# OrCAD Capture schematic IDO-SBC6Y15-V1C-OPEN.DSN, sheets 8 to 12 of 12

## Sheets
8 P12 EXPAND: size A2; note: EXPAND
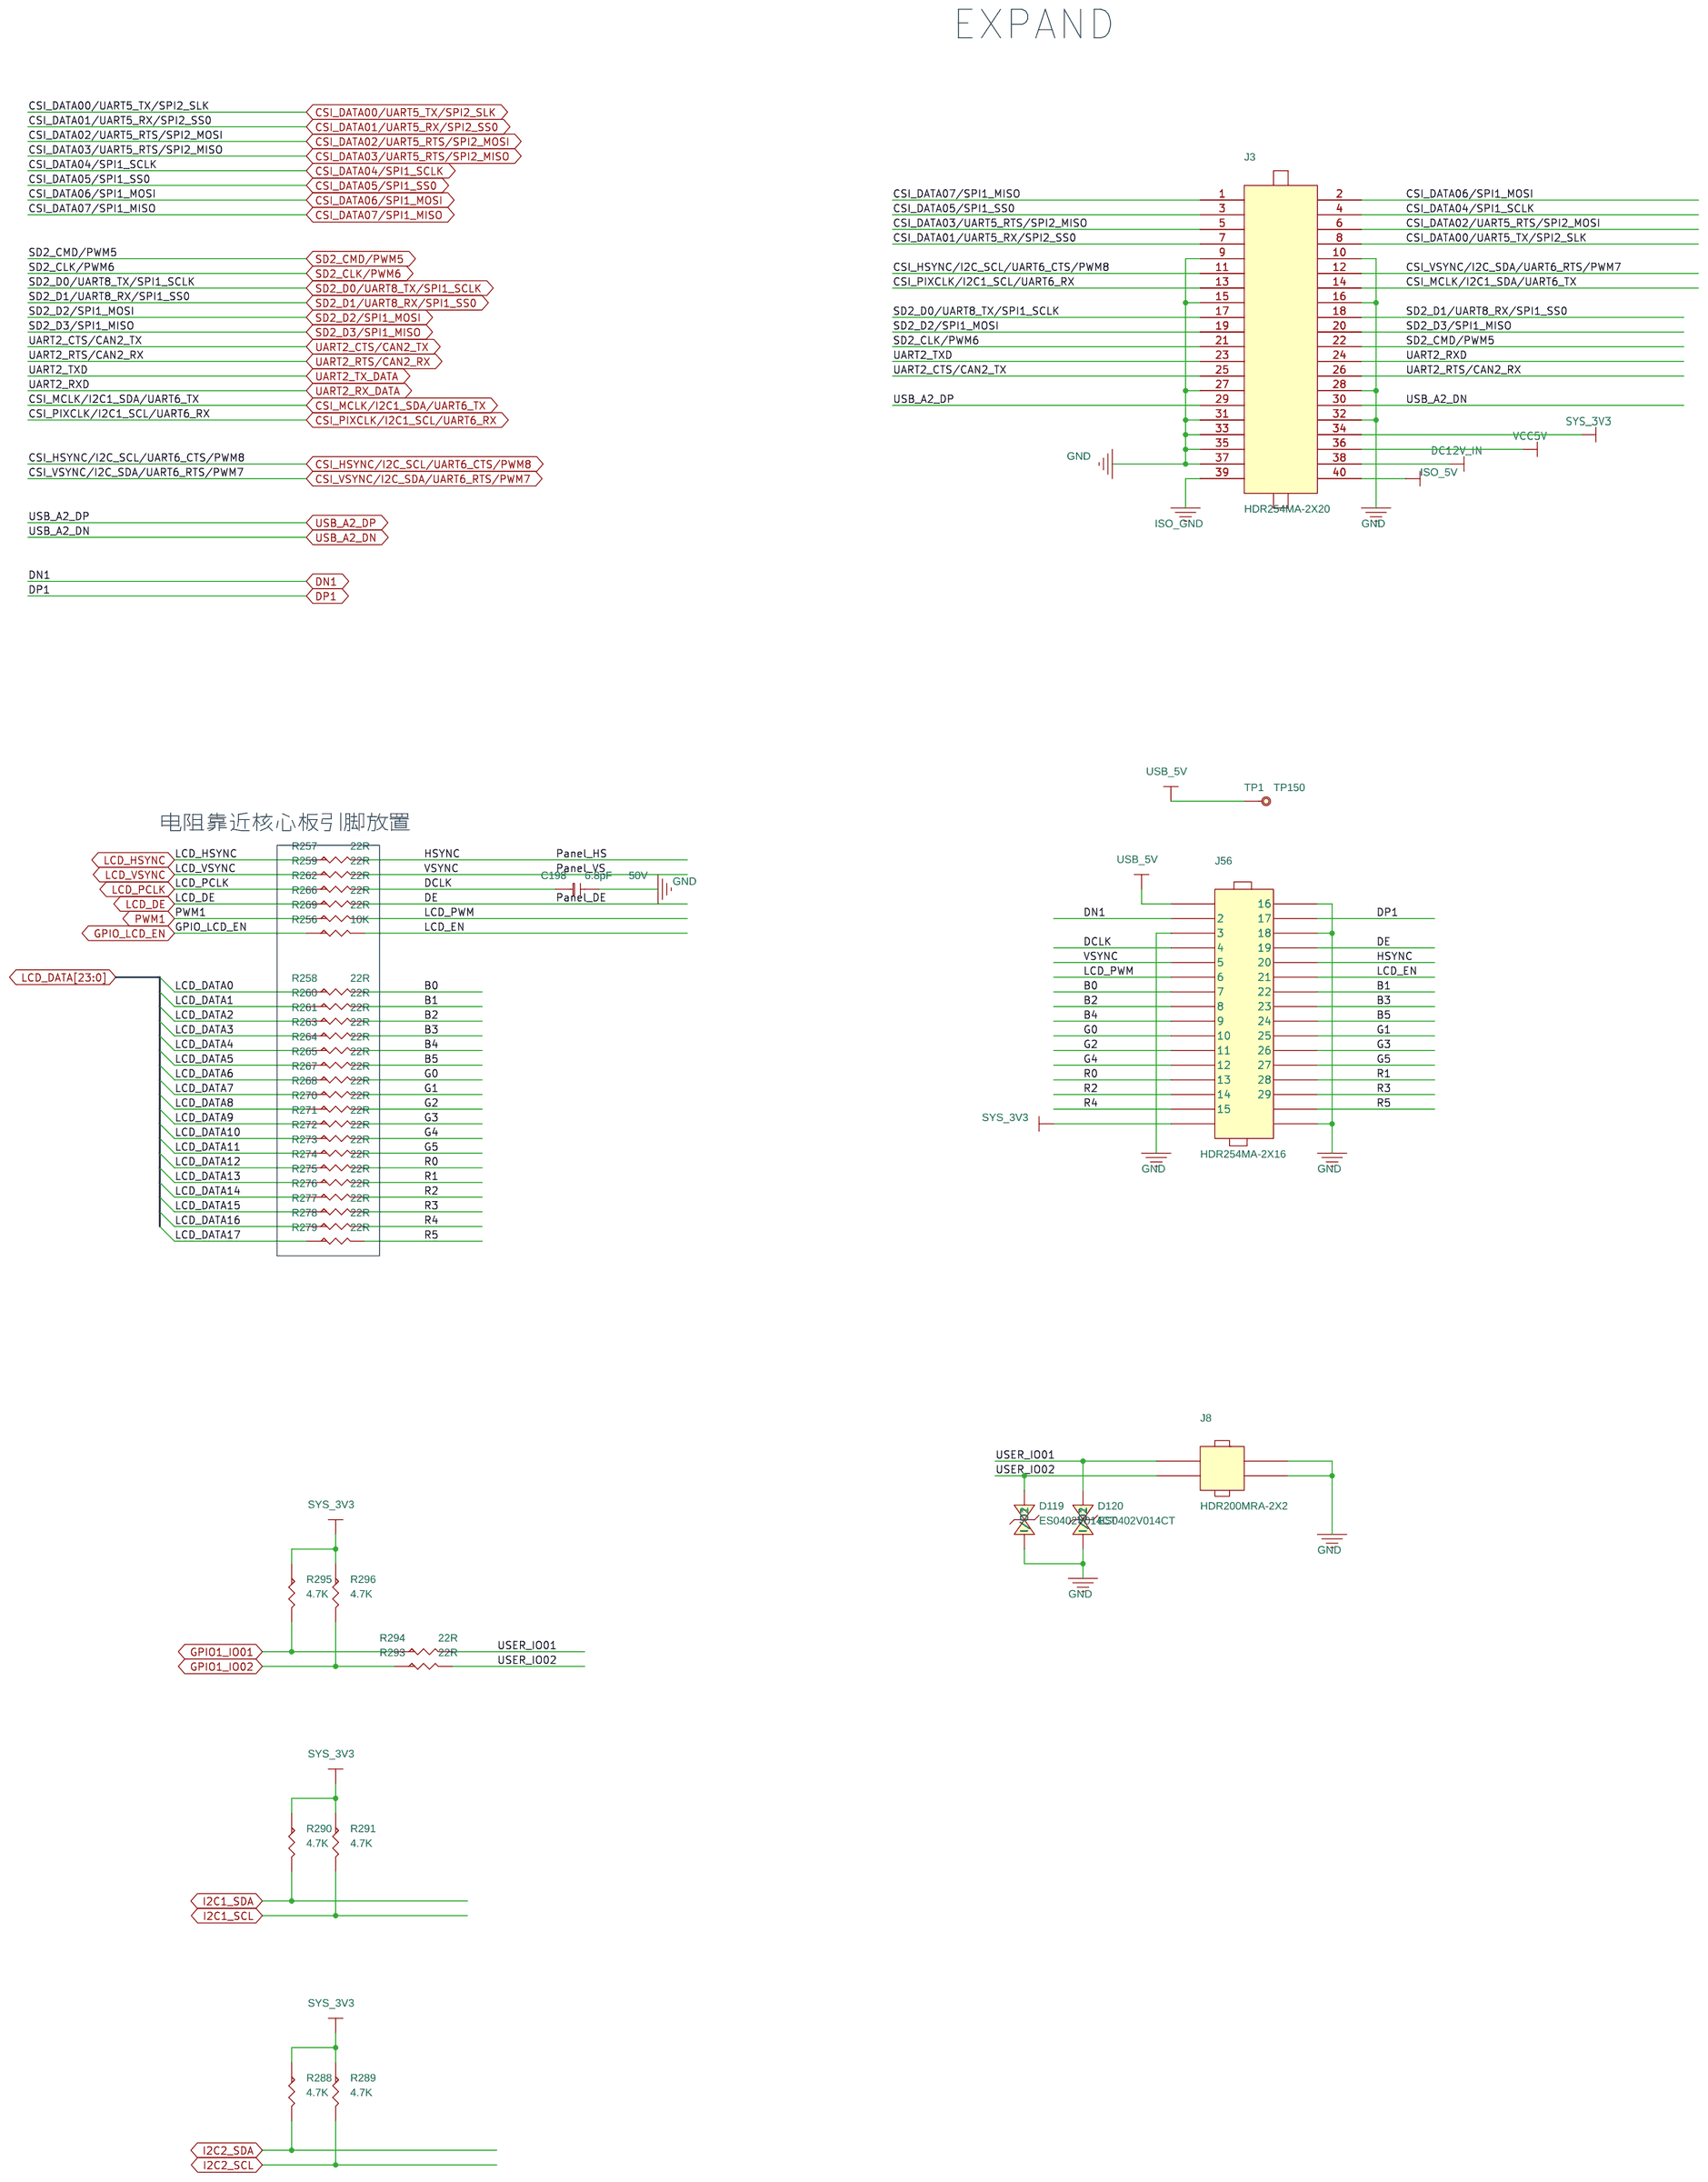
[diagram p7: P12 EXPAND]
9 P11 4G/WIFI: size A2; note: 4G/WIFI
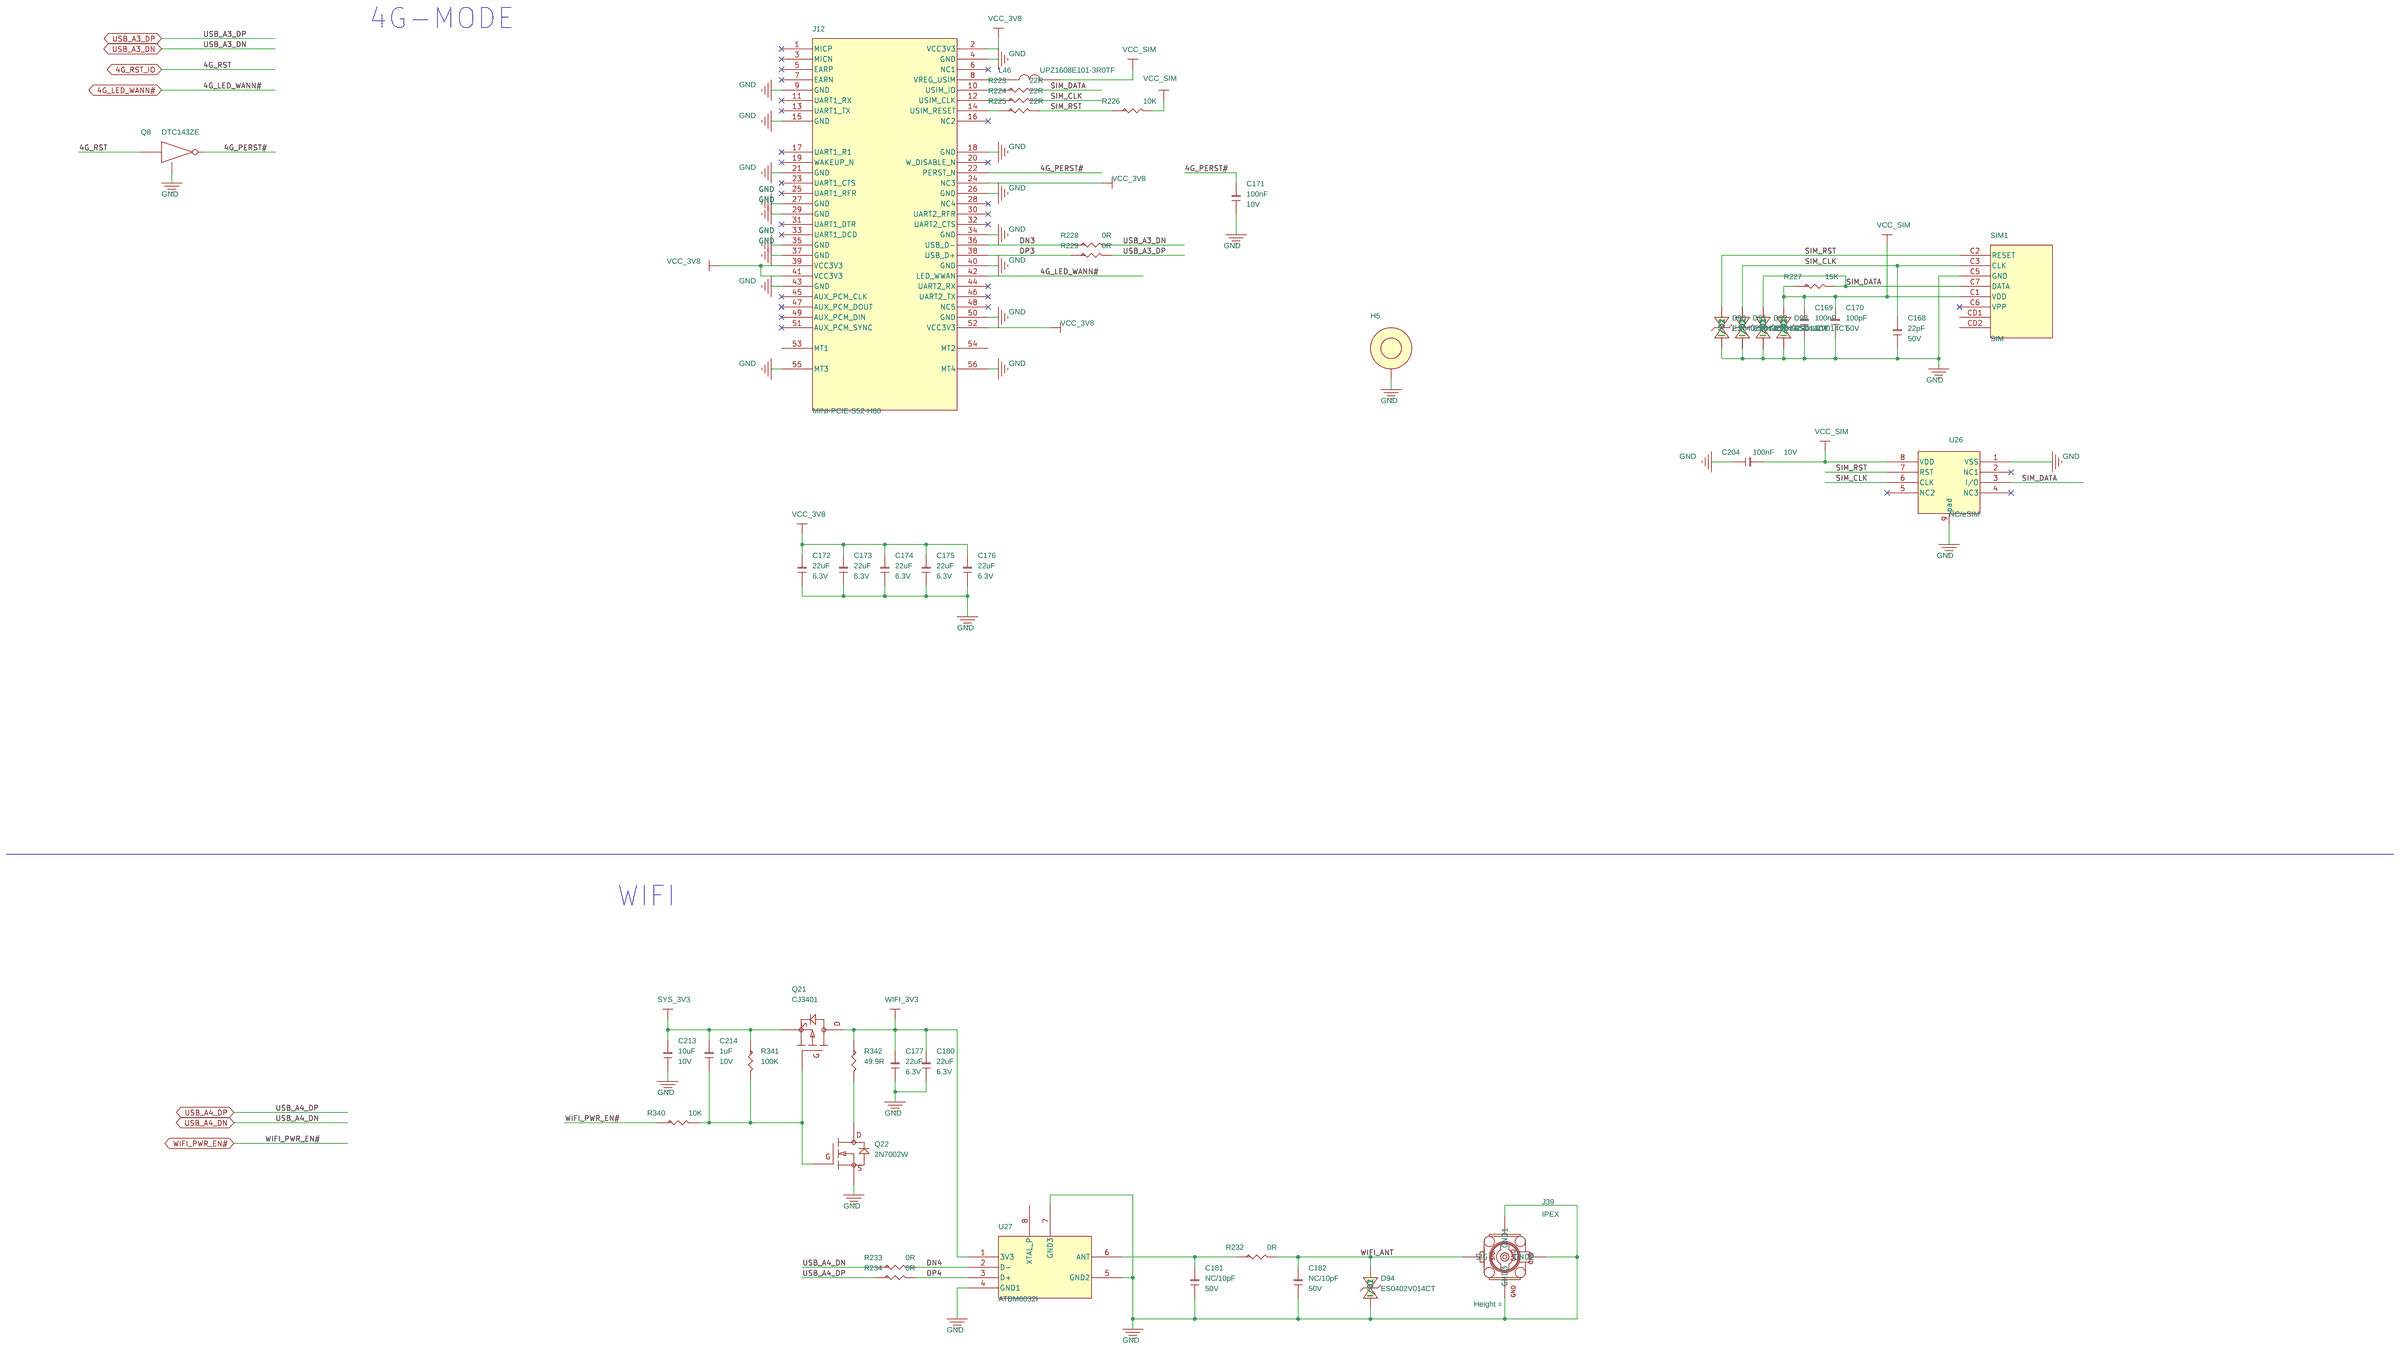
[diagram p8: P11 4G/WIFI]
10 P07 SD/RTC: size A2; note: SD/RTC
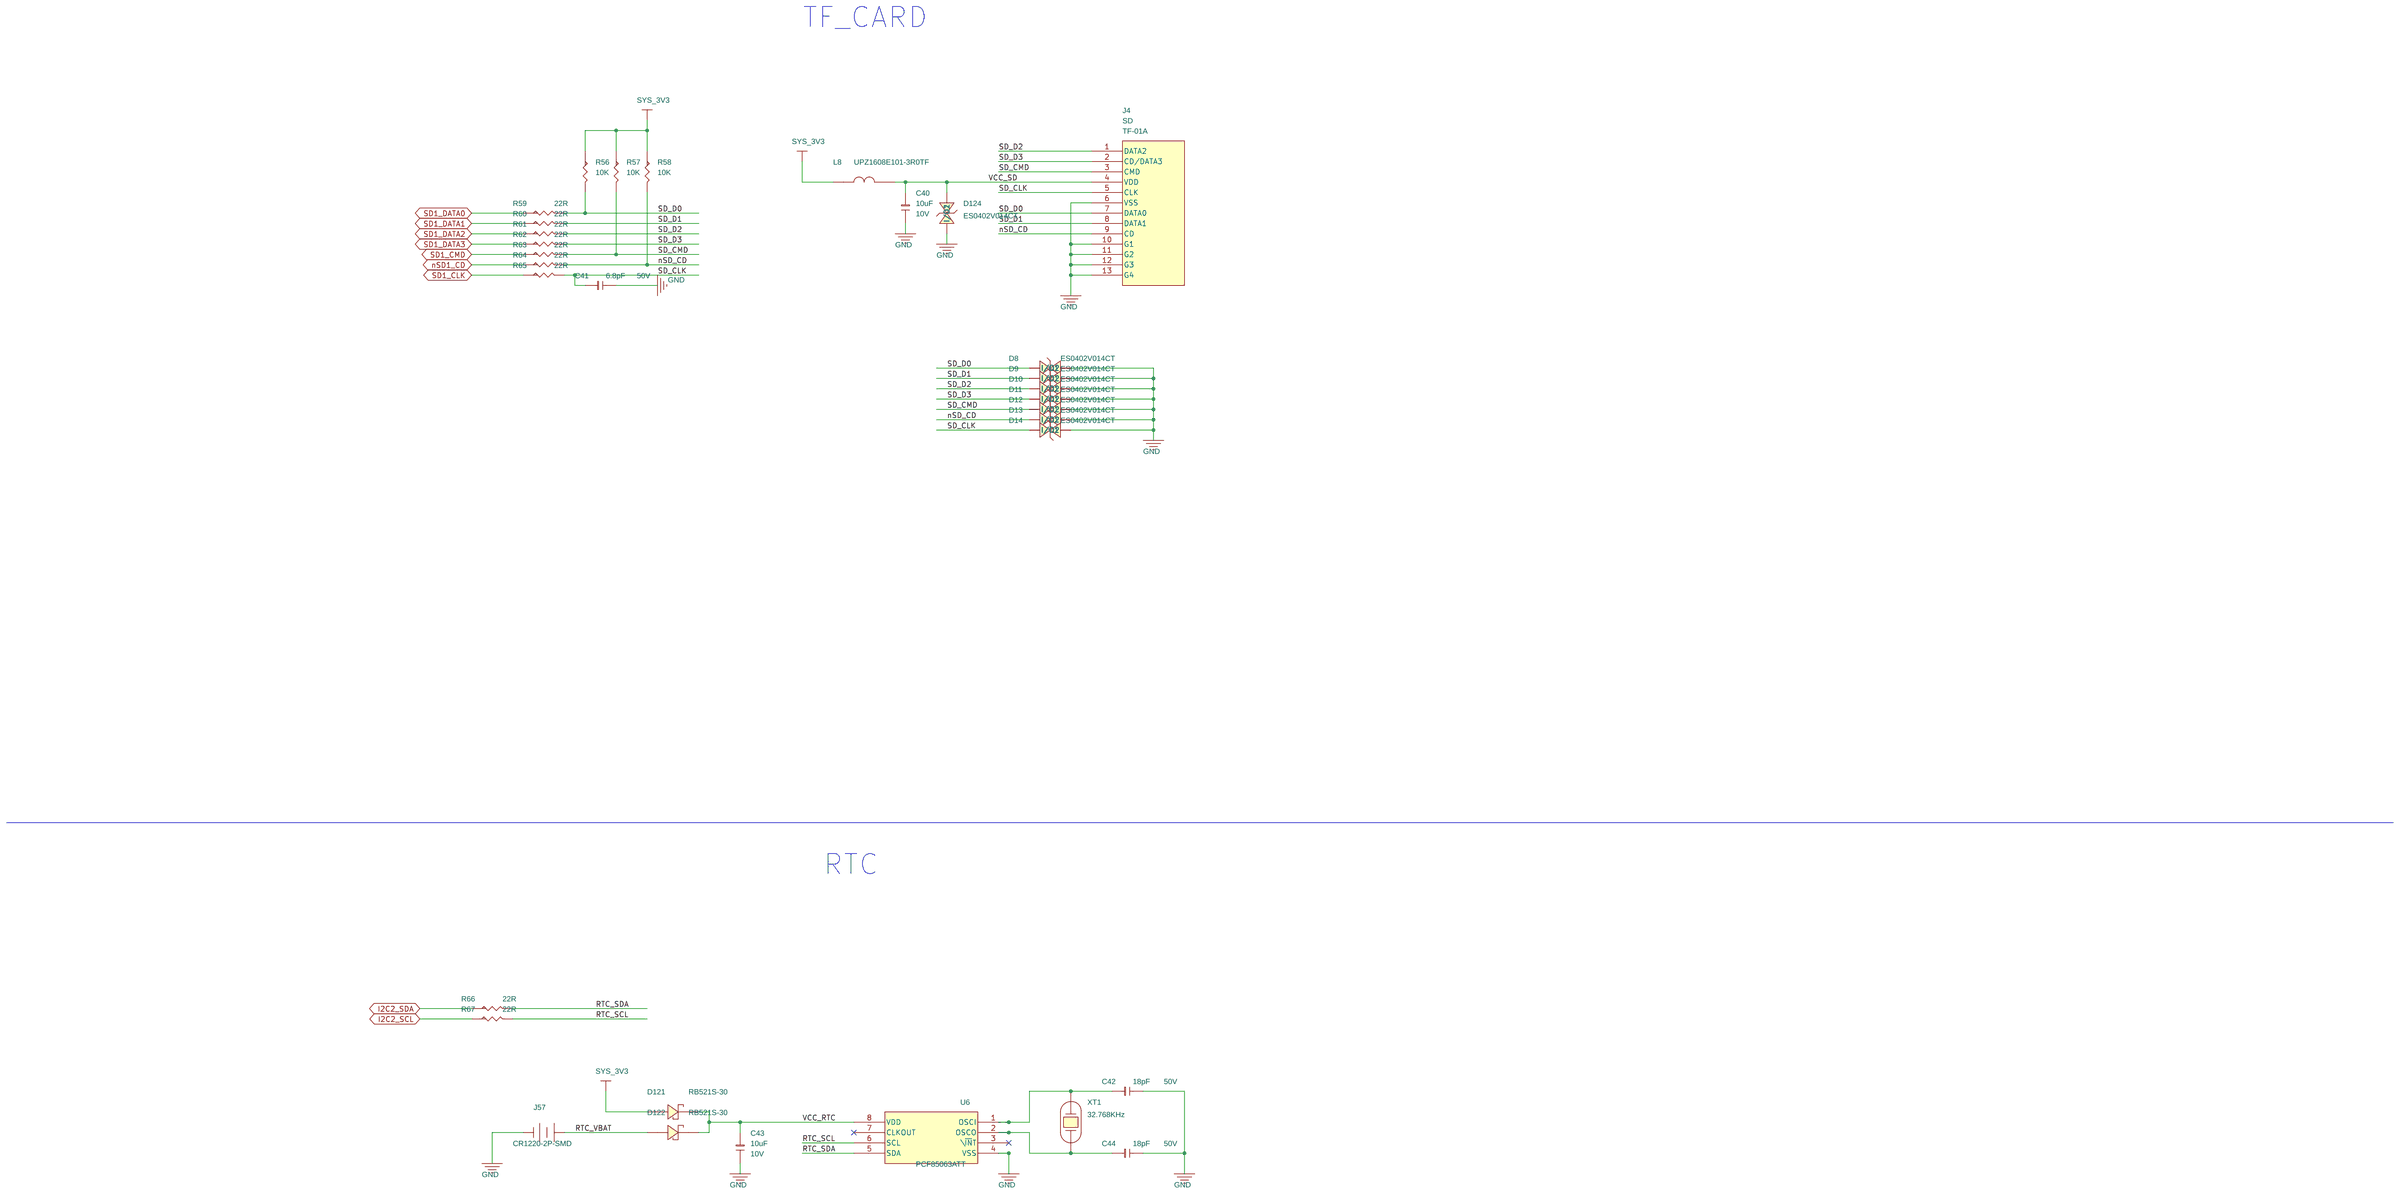
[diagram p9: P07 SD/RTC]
11 P10 UART/Debug: size A2; note: UART/Debug
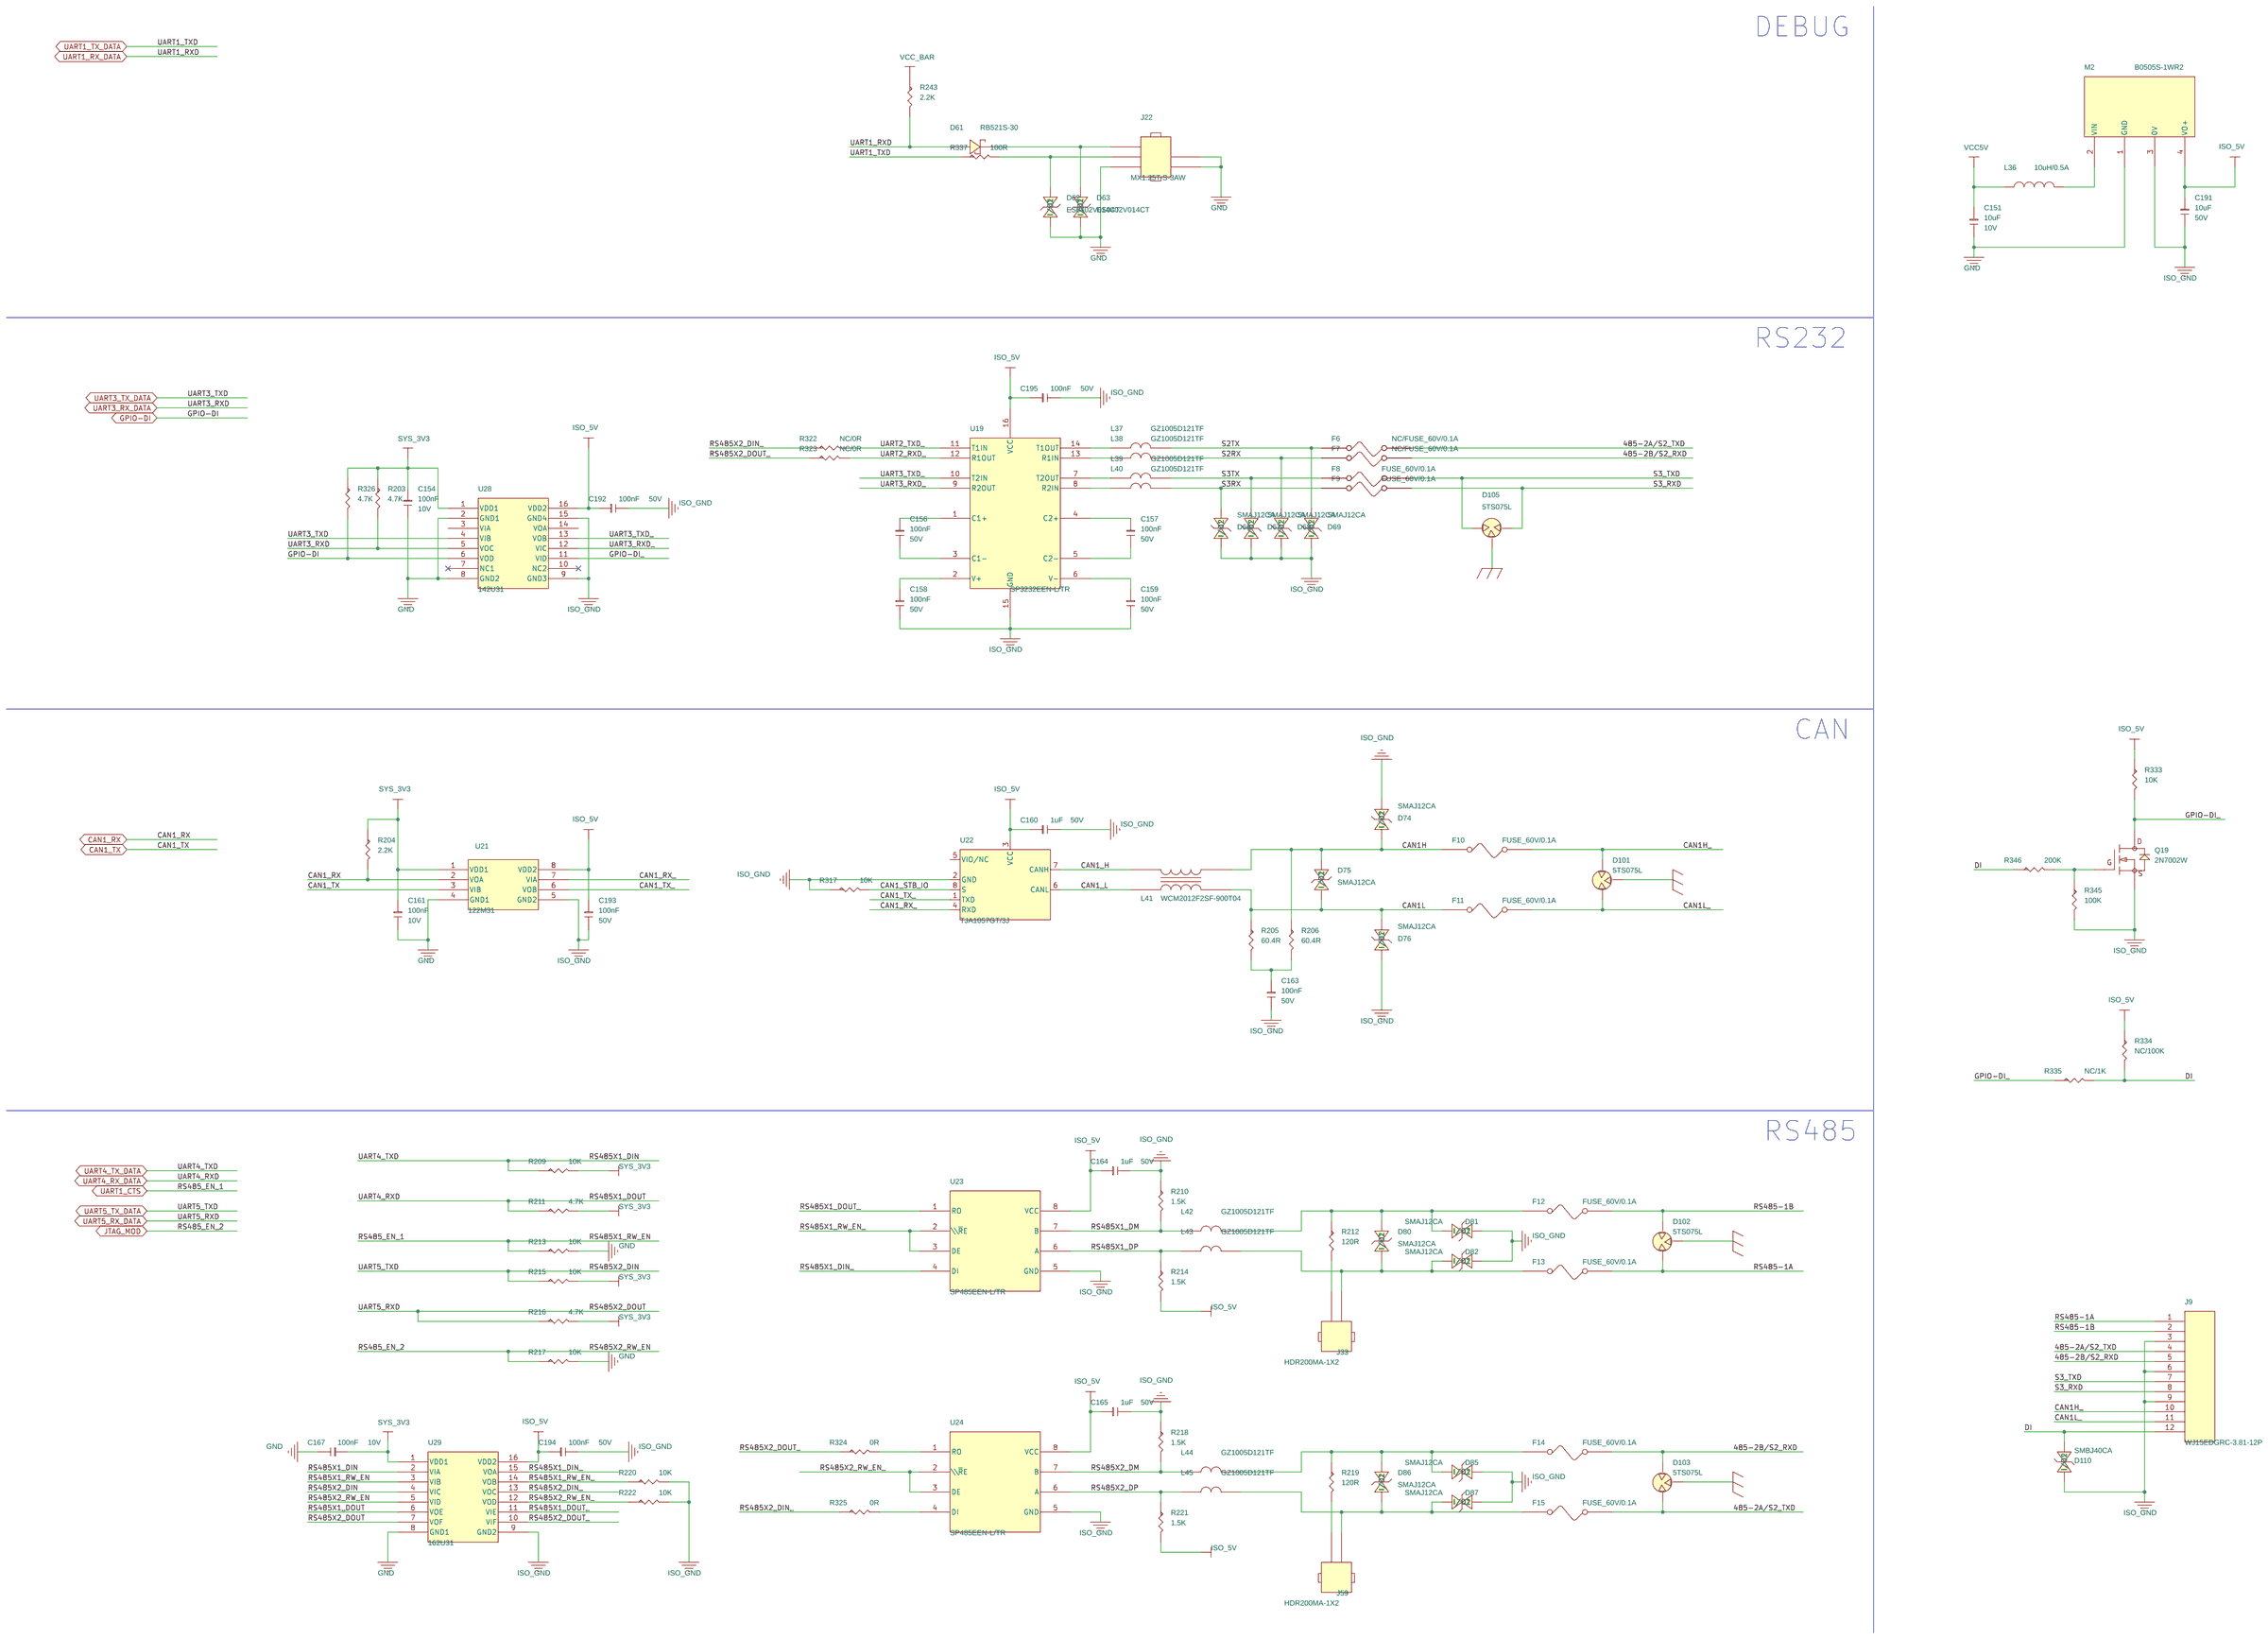
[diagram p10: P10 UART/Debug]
12 P05 POWER_SUPPLY/LED: size A2; note: POWER_SUPPY
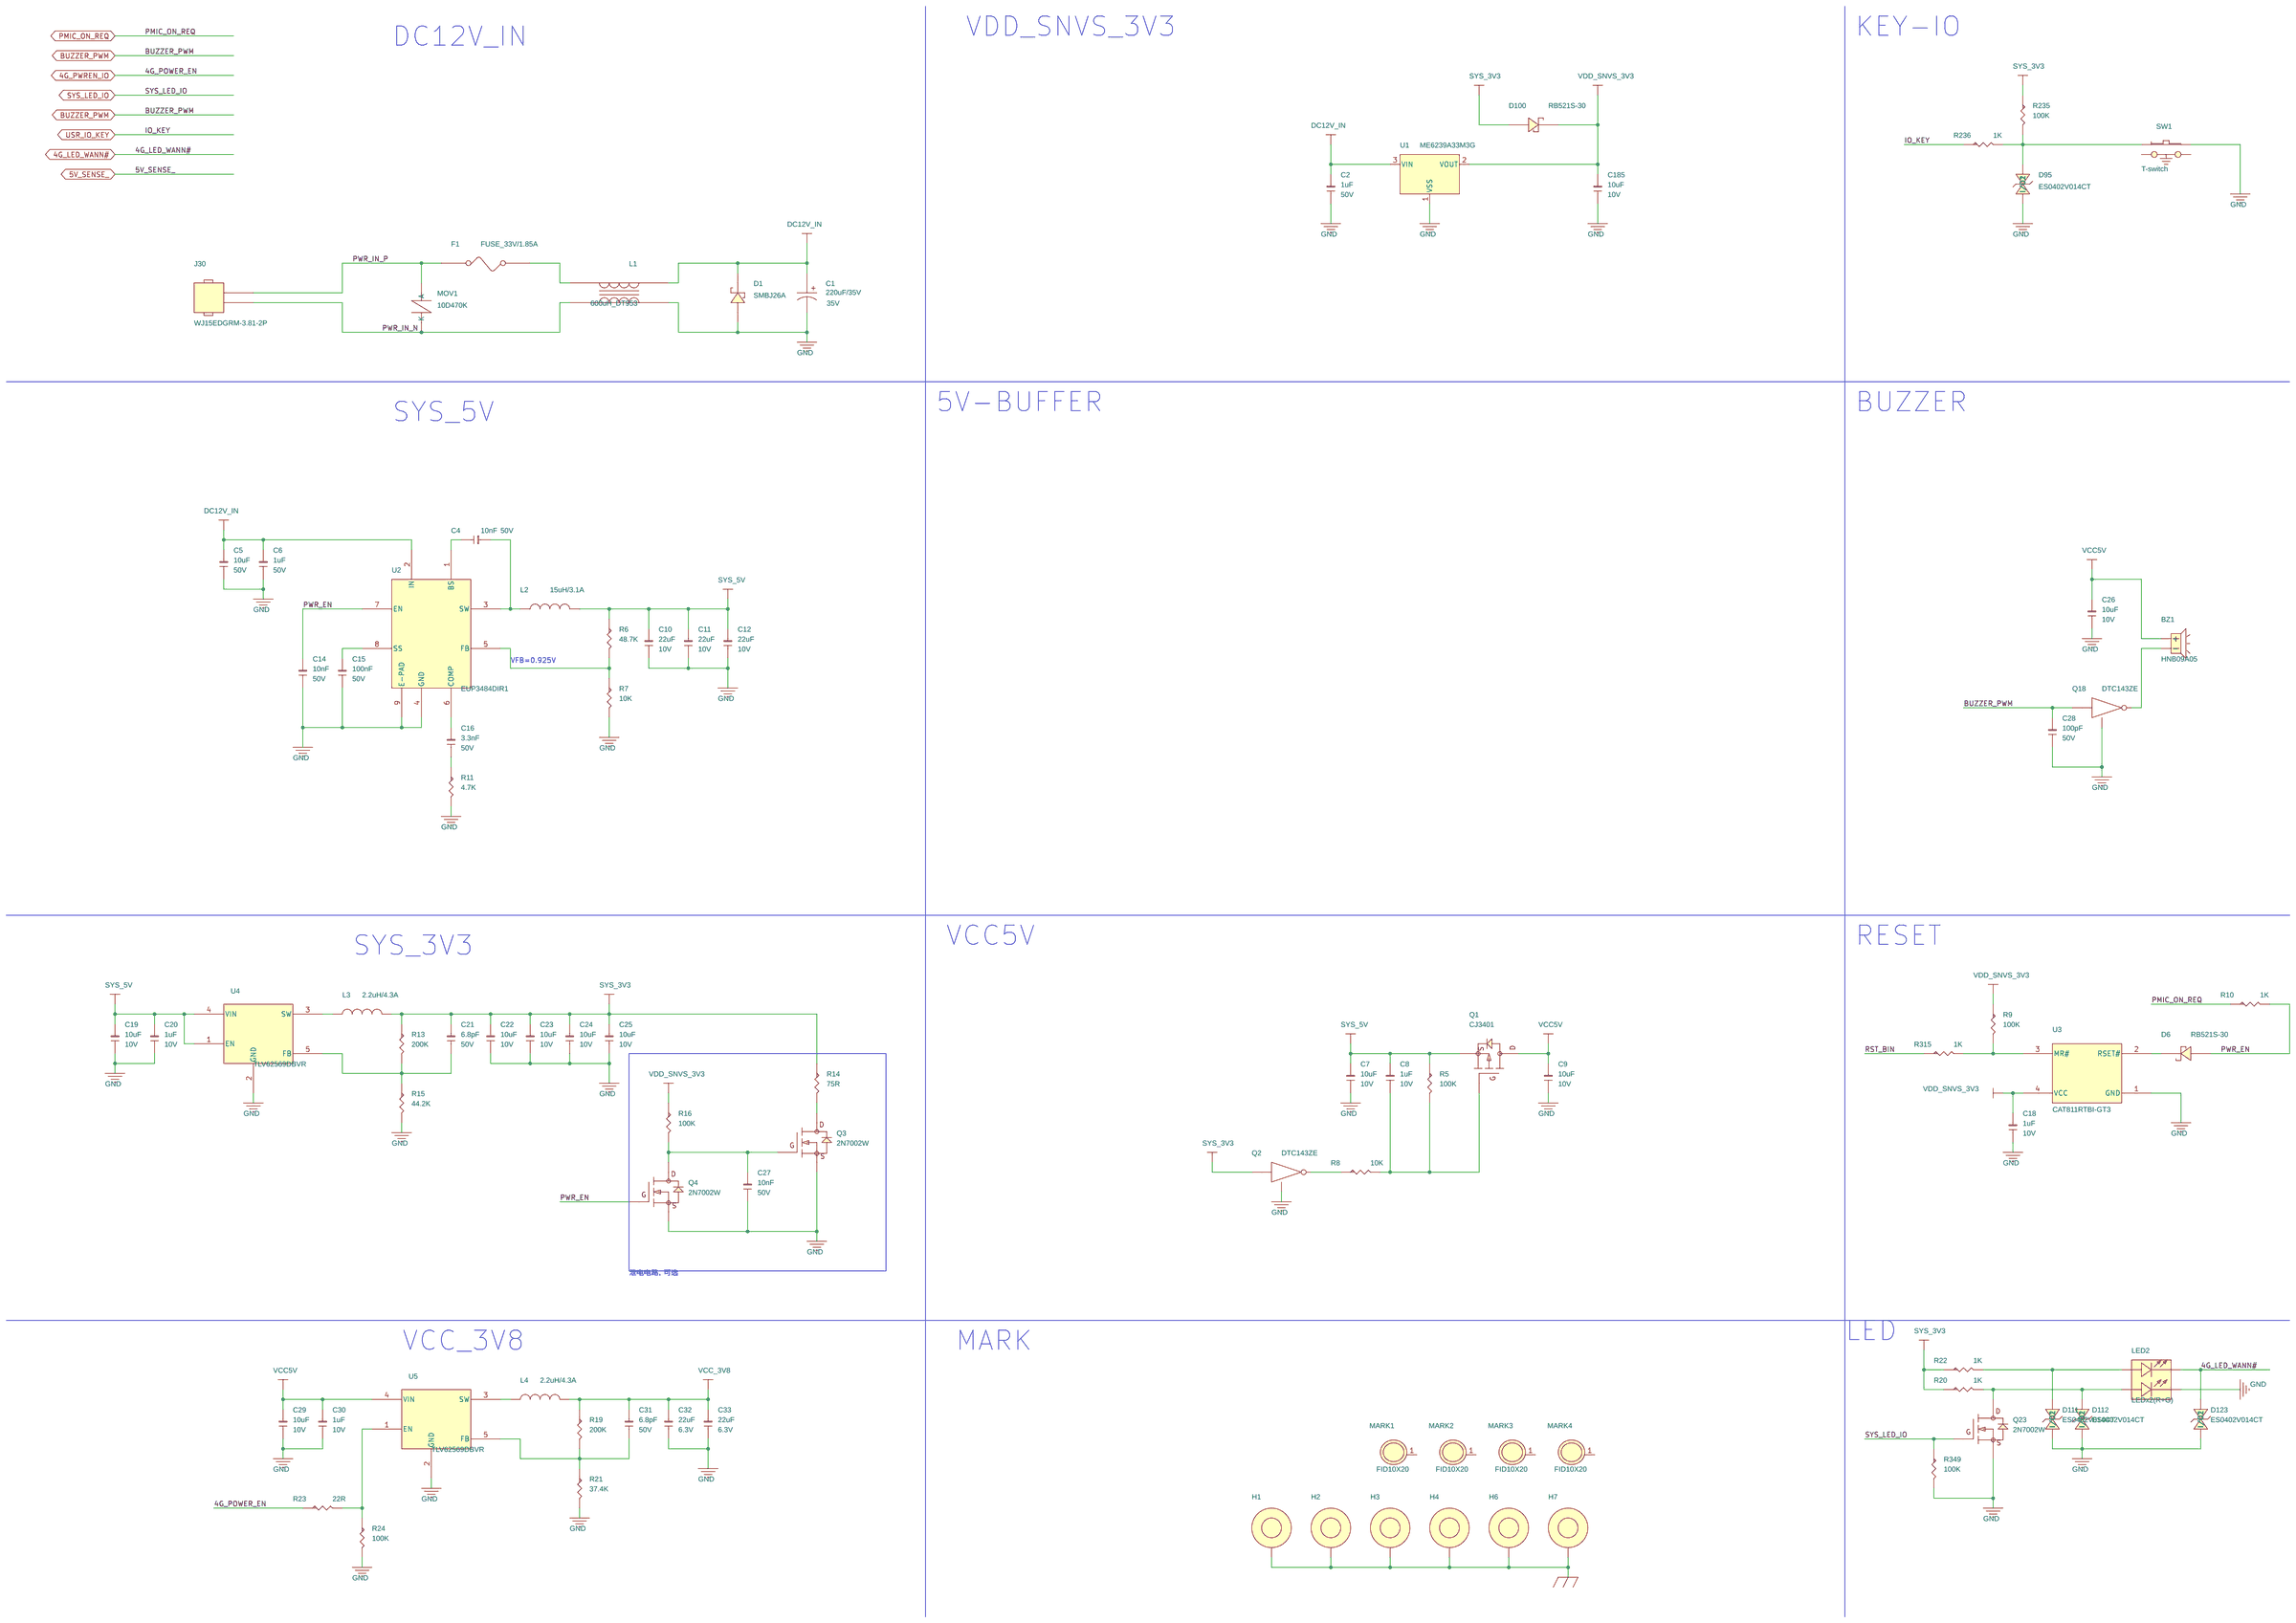
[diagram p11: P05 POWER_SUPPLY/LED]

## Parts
sheet P05 POWER_SUPPLY/LED
BZ1  HNB09A05  [buzzer_12_2-2p]
C1  220uF/35V  [CAPAE830X1050]
C2  1uF  [C0603L]
C4  10nF  [C0402L]
C5  10uF  [C1206L]
C6  1uF  [C0603L]
C7  10uF  [C0603L]
C8  1uF  [C0402L]
C9  10uF  [C0603L]
C10  22uF  [C0805L]
C11  22uF  [C0805L]
C12  22uF  [C0805L]
C14  10nF  [C0402L]
C15  100nF  [C0402L]
C16  3.3nF  [C0402L]
C18  1uF  [C0402L]
C19  10uF  [C0603L]
C20  1uF  [C0402L]
C21  6.8pF  [C0402L]
C22  10uF  [C0603L]
C23  10uF  [C0603L]
C24  10uF  [C0603L]
C25  10uF  [C0603L]
C26  10uF  [C0603L]
C27  10nF  [C0402L]
C28  100pF  [C0402L]
C29  10uF  [C0603L]
C30  1uF  [C0402L]
C31  6.8pF  [C0402L]
C32  22uF  [C0603L]
C33  22uF  [C0603L]
C185  10uF  [C0603L]
D1  SMBJ26A  [SMB_DO-214AA]
D6  RB521S-30  [SOD523]
D95  ES0402V014CT  [V0402]
D100  RB521S-30  [SOD523]
D111  ES0402V014CT  [V0402]
D112  ES0402V014CT  [V0402]
D123  ES0402V014CT  [V0402]
F1  FUSE_33V/1.85A  [SMD2920]
H1  HOLE  [mtg370_600]
H2  HOLE  [mtg370_600]
H3  HOLE  [mtg370_600]
H4  HOLE  [mtg370_600]
H6  HOLE  [mtg370_600]
H7  HOLE  [mtg370_600]
J30  WJ15EDGRM-3.81-2P  [WJ15EDGRM-381T-2P]
L1  600uH_DT953  [CMLP-DT953]
L2  15uH/3.1A  [LM73x66]
L3  2.2uH/4.3A  [L4040]
L4  2.2uH/4.3A  [L4040]
LED2  LEDx2(R+G)  [LED_P254_2X2DIP]
MARK1  FID10X20  [FID10X20]
MARK2  FID10X20  [FID10X20]
MARK3  FID10X20  [FID10X20]
MARK4  FID10X20  [FID10X20]
MOV1  10D470K  [10D-SIP2-750]
Q1  CJ3401  [SOT23]
Q2  DTC143ZE  [SOT523]
Q3  2N7002W  [SOT323]
Q4  2N7002W  [SOT323]
Q18  DTC143ZE  [SOT523]
Q23  2N7002W  [SOT323]
R5  100K  [R0402L]
R6  48.7K  [R0402l]
R7  10K  [R0402L]
R8  10K  [R0402L]
R9  100K  [R0402L]
R10  1K  [R0402L]
R11  4.7K  [R0402L]
R13  200K  [R0402L]
R14  75R  [R0402L]
R15  44.2K  [R0402L]
R16  100K  [R0402L]
R19  200K  [R0402L]
R20  1K  [R0402L]
R21  37.4K  [R0402L]
R22  1K  [R0402L]
R23  22R  [R0402L]
R24  100K  [R0402L]
R235  100K  [R0402L]
R236  1K  [R0402L]
R315  1K  [R0402L]
R349  100K  [R0402L]
SW1  T-switch  [PB-SIDE-S-3x6]
U1  ME6239A33M3G  [SOT23]
U2  EUP3484DIR1  [ESOP8-P127-390X490]
U3  CAT811RTBI-GT3  [SOT143]
U4  TLV62569DBVR  [SOT23-5]
U5  TLV62569DBVR  [SOT23-5]
sheet P07 SD/RTC
C40  10uF  [C0603L]
C41  6.8pF  [C0402L]
C42  18pF  [C0402L]
C43  10uF  [C0603L]
C44  18pF  [C0402L]
D8  ES0402V014CT  [V0402]
D9  ES0402V014CT  [V0402]
D10  ES0402V014CT  [V0402]
D11  ES0402V014CT  [V0402]
D12  ES0402V014CT  [V0402]
D13  ES0402V014CT  [V0402]
D14  ES0402V014CT  [V0402]
D121  RB521S-30  [SOD523]
D122  RB521S-30  [SOD523]
D124  ES0402V014CT  [V0402]
J4  SD  [TF-01A]
J57  CR1220-2P-SMD  [CR1220-2P-SMD]
L8  UPZ1608E101-3R0TF  [L0603]
R56  10K  [R0402L]
R57  10K  [R0402L]
R58  10K  [R0402L]
R59  22R  [R0402L]
R60  22R  [R0402L]
R61  22R  [R0402L]
R62  22R  [R0402L]
R63  22R  [R0402L]
R64  22R  [R0402L]
R65  22R  [R0402L]
R66  22R  [R0402L]
R67  22R  [R0402L]
U6  PCF85063ATT  [PCF85063ATT-TSSOP8]
XT1  32.768KHz  [XTAL_32X15_2P]
sheet P10 UART/Debug
C151  10uF  [C0603L]
C154  100nF  [C0402L]
C156  100nF  [C0402L]
C157  100nF  [C0402L]
C158  100nF  [C0402L]
C159  100nF  [C0402L]
C160  1uF  [C0603L]
C161  100nF  [C0402L]
C163  100nF  [C0402L]
C164  1uF  [C0603L]
C165  1uF  [C0603L]
C167  100nF  [C0402L]
C191  10uF  [C1206L]
C192  100nF  [C0402L]
C193  100nF  [C0402L]
C194  100nF  [C0402L]
C195  100nF  [C0402L]
D61  RB521S-30  [SOD523]
D62  ES0402V014CT  [V0402]
D63  ES0402V014CT  [V0402]
D66  SMAJ12CA  [SMA_DO-214AC]
D67  SMAJ12CA  [SMA_DO-214AC]
D68  SMAJ12CA  [SMA_DO-214AC]
D69  SMAJ12CA  [SMA_DO-214AC]
D74  SMAJ12CA  [SMA_DO-214AC]
D75  SMAJ12CA  [SMA_DO-214AC]
D76  SMAJ12CA  [SMA_DO-214AC]
D80  SMAJ12CA  [SMA_DO-214AC]
D81  SMAJ12CA  [SMA_DO-214AC]
D82  SMAJ12CA  [SMA_DO-214AC]
D85  SMAJ12CA  [SMA_DO-214AC]
D86  SMAJ12CA  [SMA_DO-214AC]
D87  SMAJ12CA  [SMA_DO-214AC]
D101  5TS075L  [SMD-GDT-3RM-50X75]
D102  5TS075L  [SMD-GDT-3RM-50X75]
D103  5TS075L  [SMD-GDT-3RM-50X75]
D105  5TS075L  [SMD-GDT-3RM-50X75]
D110  SMBJ40CA  [SMB_DO-214AA]
F6  NC/FUSE_60V/0.1A  [SMD1206]
F7  NC/FUSE_60V/0.1A  [SMD1206]
F8  FUSE_60V/0.1A  [SMD1206]
F9  FUSE_60V/0.1A  [SMD1206]
F10  FUSE_60V/0.1A  [SMD1206]
F11  FUSE_60V/0.1A  [SMD1206]
F12  FUSE_60V/0.1A  [SMD1206]
F13  FUSE_60V/0.1A  [SMD1206]
F14  FUSE_60V/0.1A  [SMD1206]
F15  FUSE_60V/0.1A  [SMD1206]
J9  WJ15EDGRC-3.81-12P  [WJ15EDGR-381T-12P]
J22  MX1.25T-S-3AW  [MX125T-S-3AW]
J33  HDR200MA-1X2  [HDR200MA-1X2]
J59  HDR200MA-1X2  [HDR200MA-1X2]
L36  10uH/0.5A  [L2520]
L37  GZ1005D121TF  [L0402]
L38  GZ1005D121TF  [L0402]
L39  GZ1005D121TF  [L0402]
L40  GZ1005D121TF  [L0402]
L41  WCM2012F2SF-900T04  [CMLS-ACM2012]
L42  GZ1005D121TF  [L0402]
L43  GZ1005D121TF  [L0402]
L44  GZ1005D121TF  [L0402]
L45  GZ1005D121TF  [L0402]
M2  B0505S-1WR2  [B0505S-1WR2-SIP4]
Q19  2N7002W  [SOT323]
R203  4.7K  [R0402L]
R204  2.2K  [R0402L]
R205  60.4R  [R0603L]
R206  60.4R  [R0603L]
R209  10K  [R0402L]
R210  1.5K  [R0603L]
R211  4.7K  [R0402L]
R212  120R  [R1206L]
R213  10K  [R0402L]
R214  1.5K  [R0603L]
R215  10K  [R0402L]
R216  4.7K  [R0402L]
R217  10K  [R0402L]
R218  1.5K  [R0603L]
R219  120R  [R1206L]
R220  10K  [R0402L]
R221  1.5K  [R0603L]
R222  10K  [R0402L]
R243  2.2K  [R0402L]
R317  10K  [R0402L]
R322  NC/0R  [R0402L]
R323  NC/0R  [R0402L]
R324  0R  [R0402L]
R325  0R  [R0402L]
R326  4.7K  [R0402L]
R333  10K  [R0402L]
R334  NC/100K  [R0402L]
R335  NC/1K  [R0402L]
R337  100R  [R0402L]
R345  100K  [R0402L]
R346  200K  [R0402L]
U19  SP3232EEN-L/TR  [SP3232EEN-SOP16]
U21  122M31  [SOP8-P127-390X490]
U22  TJA1057GT/3J  [SOP8-P127-390X490]
U23  SP485EEN-L/TR  [SOP8-P127-390X490]
U24  SP485EEN-L/TR  [SOP8-P127-390X490]
U28  142U31  [142U31-SOP16]
U29  162U31  [162U31-SOP16]
sheet P11 4G/WIFI
C168  22pF  [C0402L]
C169  100nF  [C0402L]
C170  100pF  [C0402L]
C171  100nF  [C0402L]
C172  22uF  [C0603L]
C173  22uF  [C0603L]
C174  22uF  [C0603L]
C175  22uF  [C0603L]
C176  22uF  [C0603L]
C177  22uF  [C0603L]
C180  22uF  [C0603L]
C181  NC/10pF  [C0402L]
C182  NC/10pF  [C0402L]
C204  100nF  [C0402L]
C213  10uF  [C0603L]
C214  1uF  [C0402L]
D90  ES0402V014CT  [V0402]
D91  ES0402V014CT  [V0402]
D92  ES0402V014CT  [V0402]
D93  ES0402V014CT  [V0402]
D94  ES0402V014CT  [V0402]
H5  HOLE  [mtg250_600]
J12  MINI-PCIE-S52-H80  [M_MINIPCIE_SOCKET_CK]
J39  IPEX  [IPEX-20279-001E]
L46  UPZ1608E101-3R0TF  [L0603]
Q8  DTC143ZE  [SOT523]
Q21  CJ3401  [SOT23]
Q22  2N7002W  [SOT323]
R223  22R  [R0402L]
R224  22R  [R0402L]
R225  22R  [R0402L]
R226  10K  [R0402L]
R227  15K  [R0402L]
R228  0R  [R0402L]
R229  0R  [R0402L]
R232  0R  [R0402L]
R233  0R  [R0402L]
R234  0R  [R0402L]
R340  10K  [R0402L]
R341  100K  [R0402L]
R342  49.9R  [R0402L]
SIM1  SIM  [SIM-91288-021]
U26  NC/eSIM  [esim]
U27  ATBM6032I  [ATBM6032I]
sheet P12 EXPAND
C198  6.8pF  [C0402L]
D119  ES0402V014CT  [V0402]
D120  ES0402V014CT  [V0402]
J3  HDR254MA-2X20  [HDR254MA-2X20]
J8  HDR200MRA-2X2  [HDR200MRA-2X2]
J56  HDR254MA-2X16  [HDR254MA-2X16]
R256  10K  [R0402L]
R257  22R  [R0402L]
R258  22R  [R0402L]
R259  22R  [R0402L]
R260  22R  [R0402L]
R261  22R  [R0402L]
R262  22R  [R0402L]
R263  22R  [R0402L]
R264  22R  [R0402L]
R265  22R  [R0402L]
R266  22R  [R0402L]
R267  22R  [R0402L]
R268  22R  [R0402L]
R269  22R  [R0402L]
R270  22R  [R0402L]
R271  22R  [R0402L]
R272  22R  [R0402L]
R273  22R  [R0402L]
R274  22R  [R0402L]
R275  22R  [R0402L]
R276  22R  [R0402L]
R277  22R  [R0402L]
R278  22R  [R0402L]
R279  22R  [R0402L]
R288  4.7K  [R0402L]
R289  4.7K  [R0402L]
R290  4.7K  [R0402L]
R291  4.7K  [R0402L]
R293  22R  [R0402L]
R294  22R  [R0402L]
R295  4.7K  [R0402L]
R296  4.7K  [R0402L]
TP1  TP150  [TP150]

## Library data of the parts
BZ1 = BZ-HNB09A05: DSC1: 9*5.5mm，直插; DSC2: 有源蜂鸣器,5V; ID: 1; Part Name: 蜂鸣器; Part Number: C210102740001
C1 = C-AL-SMD: DSC1: ±20%; DSC2: 35V; DSC3: 低阻抗长寿命; DSC4: 5000H; DSC5: -55~105 ℃; DSC6: SMD,8x10.5mm; DSC7: FZ1V221M-CRF10(ST); DSC8: VZH221M1VTR-0810(立隆); ID: 13; Manufacture: 先科|立隆|三莹; Part Name: 贴片铝电容; Part Number: C020302140013; Price: 0.50
C2 C6 C160 C164 C165 = C-0603: DSC1: ±10%; DSC2: 50V; DSC3: X5R; ERP Number: 1010200142; ID: 69; Manufacture: 三星|国巨|村田; Part Name: 贴片电容; Part Number: C020102120069; Price: 0.04
C4 C14 C27 = C-0402: DSC1: ±10%; DSC2: 50V; DSC3: X7R; ERP Number: 1010200077; ID: 57; Manufacture: 三星|国巨|村田; Part Name: 贴片电容; Part Number: C020102120057; Price: 0.02
C5 C191 = C-1206: DSC1: ±10%; DSC2: 50V; DSC3: X5R; ID: 79; Manufacture: 三星|国巨|村田; Part Name: 贴片电容; Part Number: C020103263826; Price: 0.24
C7 C9 C19 C22-C26 C29 C40 C43 C151 C185 C213 = C-0603: DSC1: ±20%; DSC2: 10V; DSC3: X5R; ERP Number: 1010200076; ID: 71; Manufacture: 三星|国巨|村田; Part Name: 贴片电容; Part Number: C020102120071; Price: 0.05
C8 C18 C20 C30 C214 = C-0402: DSC1: ±10%; DSC2: 10V; DSC3: X5R; ERP Number: 1010200054; ID: 64; Manufacture: 三星|国巨|村田; Part Name: 贴片电容; Part Number: C020102120064; Price: 0.02
C10-C12 = C-0805: DSC1: ±20%; DSC2: 10V; DSC3: X5R; ID: 75; Manufacture: 三星|国巨|村田; Part Name: 贴片电容; Part Number: C020102120075; Price: 0.11
C15 C156-C159 C163 C192-C195 = C-0402: DSC1: ±10%; DSC2: 50V; DSC3: X7R; ERP Number: 1010200128; ID: 61; Manufacture: 三星|国巨|村田; Part Name: 贴片电容; Part Number: C020102120061; Price: 0.05
C16 = C-0402: DSC1: ±10%; DSC2: 50V; DSC3: X7R; ID: 81; Manufacture: 三星|国巨|村田; Part Name: 贴片电容; Part Number: C020104013836; Price: 0.01
C21 C31 C41 C198 = C-0402: DSC1: ±0.25PF; DSC2: 50V; DSC3: C0G; ERP Number: 1010200056; ID: 18; Manufacture: 三星|国巨|村田; Part Name: 贴片电容; Part Number: C020102120018; Price: 0.01
C28 C170 = C-0402: DSC1: ±5%; DSC2: 50V; DSC3: C0G; ERP Number: 1010200152; ID: 40; Manufacture: 三星|国巨|村田; Part Name: 贴片电容; Part Number: C020102120040; Price: 0.01
C32 C33 C172-C177 C180 = C-0603: DSC1: ±20%; DSC2: 6.3V; DSC3: X5R; ERP Number: 1010200133; ID: 72; Manufacture: 三星|国巨|村田; Part Name: 贴片电容; Part Number: C020102120072; Price: 0.06
D1 = DI-XI-S: DSC1: 单向; DSC2: Vrwm=26V; DSC3: VBR=28.9V; DSC4: Vc=42.1V; DSC5: Ipp=14.2A; DSC6: Ppp=800W; ERP Number: 1010800043; ID: 7; Manufacture: MDD|伯恩半导体; Part Name: TVS; Part Number: C040602260007
D6 D61 D100 D121 D122 = DI-XI-S: DSC1: VR=30V; DSC2: IF=200mA; DSC3: VF=100mV/10mA; DSC4: IR=30uA; ERP Number: 1010800004; ID: 15; Manufacture: 长电; Part Name: 肖特基二级管; Part Number: C040202220015; Price: 0.05; Solder: 量产
D8-D14 D62 D63 D90-D95 D111 D112 D119 D120 D123 D124 = DI-ESD: DSC1: 双向; DSC2: Vdc=14V; DSC3: Vbr=300V; DSC4: Vc=30V; DSC5: Cj=0.25pF; ERP Number: 1010800023; ID: 2; Manufacture: AEM; Part Name: ESD; Part Number: C040502250002; Price: 0.06
F1 = FUSE-SMD2920: DSC1: 33V; DSC2: 1.85A; DSC3: SMD2920P185TF; ID: 10; Manufacture: RUILON; Part Name: 自恢复保险丝; Part Number: C160102670010; Price: 0.38
H1-H7 = HOLE
J30 = J-PCB-Con-2P: DSC1: 3.81mm; DSC2: 2P; DSC3: 通孔弯针; DSC4: 绿色 带法兰; DSC5: WJ15EDGRM-3.81-2P(康奈克斯); ID: 42; Part Name: PCB插拔式接线端子; Part Number: J040202890080
L1 = L-600uH_DT953: DSC1: 600uH; DSC3: 2A; DSC6: 9*5*3mm,0.5线 四脚插件; ID: 8; Part Name: 电源共模电感; Part Number: C060402360008; Price: 0.3
L2 = L-IND: DSC1: ±20%; DSC2: Isat=4.6A; DSC3: Irms=3.1A; DSC4: 112mΩ; DSC5: 7.3*6.6*3.0mm; DSC6: SMMS0630-150M(顺翔诺); DSC7: FXL0630-150-M(长江微电); ID: 41; Manufacture: 顺翔诺|长江微电); Part Name: 功率电感; Part Number: C060202340041; Price: 0.47
L3 L4 = L-IND: DSC1: ±20%; DSC2: Isat=6.1A; DSC3: Irms=4.3A; DSC4: 48mΩ; DSC5: 4.0*4.0*2.0mm; DSC6: WPN4020H2R2MT(顺络); ERP Number: 1010200404; ID: 20; Manufacture: 顺络; Part Name: 功率电感; Part Number: C060202340020; Price: 0.38
LED2 = D-LED-DIP-2: DSC1: 双孔座2位黑色方形灯柱 90度弯脚 左正右负 上红下绿; ID: 22; Part Name: LED; Part Number: C140202660018
MARK1-MARK4 = MTG240_600_NPH_0: DSC1: 禁止布线层直径=6mm; DSC2: 孔径2.4mm; ID: 11; Type Name: 无铜固定孔
MOV1 = MOV-10D470K: DSC1: 浪涌电流=500A; ERP Number: 1010200264; ID: 1; Manufacture: HEL（鸿志）; Part Name: 压敏电阻; Part Number: C010502110001; Price: 0.2
Q1 Q21 = P-MOS: DSC1: Vds=-30V; DSC2: Id=-4.2A; DSC3: Vgs(th)=1.3V; DSC4: Vgs=±12V; DSC5: pd=350mW; ERP Number: 1010800001; ID: 1; Manufacture: 长电; Part Number: C030202190001; Price: 0.17
Q2 Q8 Q18 = S-NPN: DSC1: NPN; DSC2: Ic=100mA; DSC3: Vce=50V; DSC4: 150mW; ERP Number: 1010800049; ID: 2; Manufacture: 长电; Part Name: 数字三极管; Part Number: C030302200002; Price: 0.08
Q3 Q4 Q19 Q22 Q23 = N-MOS: DSC1: Vds=60V; DSC2: Id=115mA; DSC3: Vgs(th)=2.5V; DSC4: Vgs=±20V; DSC5: pd=200mW; ERP Number: 1010800035; ID: 6; Manufacture: 长电; Part Number: C030202190006; Price: 0.1
R5 R9 R16 R24 R235 R334 R341 R345 R349 = R-0402: DSC1: ±1%; DSC2: 1/16W; ERP Number: 1010200137; ID: 976; Part Name: 贴片电阻; Part Number: C011002080976; Price: 0.01
R6 = R-0402: DSC1: ±1%; DSC2: 1/16W; ID: 937; Part Name: 贴片电阻; Part Number: C011002080937; Price: 0.01
R7 R8 R56-R58 R209 R213 R215 R217 R220 R222 R226 R256 R317 R333 R340 = R-0402: DSC1: ±1%; DSC2: 1/16W; ERP Number: 1010200140; ID: 856; Part Name: 贴片电阻; Part Number: C011002080856; Price: 0.01
R10 R20 R22 R236 R315 R335 = R-0402: DSC1: ±1%; DSC2: 1/16W; ERP Number: 1010200113; ID: 742; Part Name: 贴片电阻; Part Number: C011002080742; Price: 0.01
R11 R203 R211 R216 R288-R291 R295 R296 R326 = R-0402: DSC1: ±1%; DSC2: 1/16W; ERP Number: 1010200445; ID: 818; Part Name: 贴片电阻; Part Number: C011002080818; Price: 0.01
R13 R19 R346 = R-0402: DSC1: ±1%; DSC2: 1/16W; ERP Number: 1010200139; ID: 1,009; Part Name: 贴片电阻; Part Number: C011002081009; Price: 0.01
R14 = R-0402: DSC1: ±1%; DSC2: 1/16W; ERP Number: 1010200187; ID: 616; Part Name: 贴片电阻; Part Number: C011002080616; Price: 0.01
R15 = R-0402: DSC1: ±1%; DSC2: 1/16W; ERP Number: 1010200256; ID: 931; Part Name: 贴片电阻; Part Number: C011002080931; Price: 0.01
R21 = R-0402: DSC1: ±1%; DSC2: 1/16W; ERP Number: 1010200444; ID: 922; Part Name: 贴片电阻; Part Number: C011002080922; Price: 0.01
R23 R59-R67 R223-R225 R257-R279 R293 R294 = R-0402: DSC1: ±1%; DSC2: 1/16W; ID: 552; Part Name: 贴片电阻; Part Number: C011002080552; Price: 0.01
SW1 = SW-TS36CA: DSC1: 轻触开关 侧键 贴片 带定位柱; DSC2: SMD,3.5*7.7mm; DSC3: TS36CA-0.7(首韩); DSC4: TSA365G00D-250(博瑞泰); ID: 2; Part Name: 轻触开关; Part Number: C180102690002
U1 = U-ME6239A33M3G_1: DSC1: Vi=5-30V; DSC2: Vo=3.3V; DSC3: Io=250mA; DSC5: Iq=1.5uA; ID: 20; Manufacture: 南京微盟; Part Name: LDO; Part Number: C070102400020; Price: 0.27
U2 = U-EUP3484DIR1: DSC1: Vi=4.5-30V; DSC2: Vo=0.925-20V; DSC3: I=3A; DSC4: Vfb=0.925V; DSC5: 0.92; DSC6: 340KHz; DSC7: 同步降压; ERP Number: 1010100145; ID: 37; Manufacture: 台湾德信; Part Name: DCDC; Part Number: C070202410037; Price: 1.2; Solder: 量产
U3 = U-CAT811RTBI-GT3: DSC1: Detection Voltage: 2.63V,Active Low CMOS ouput 240mS, Iq=6uA,  Manual Reset Input; DSC2: SOT-143; DSC3: -40℃~+85℃; ID: 8; Manufacture: ON 安森美; Part Name: 复位芯片; Part Number: C110102550008; Price: 0.55
U4 U5 = U-TLV62569DBVR: DSC1: Vi=2.5-5.5V; DSC2: Vo=0.6-5.5V; DSC3: Io=2A; DSC4: Vfb=0.6V; DSC5: 0.95; DSC6: 1.5MHz; DSC7: 同步降压 轻载效率 低Iq; ID: 3; Manufacture: TI; Part Name: DCDC; Part Number: C070202410003; Price: 0.3; Solder: 推荐
C42 C44 = C-0402: DSC1: ±5%; DSC2: 50V; DSC3: C0G; ERP Number: 1010200091; ID: 27; Manufacture: 三星|国巨|村田; Part Name: 贴片电容; Part Number: C020102120027; Price: 0.02
J4 = J-TF-01A: DSC1: TF卡座 自弹式; DSC3: 贴片; DSC4: TF-01A(韩荣); ID: 2; Part Name: SD卡座; Part Number: J080102980002
J57 = RTC-CR1220-2P-SMD: DSC1: CR1220电池座 贴片 双定位柱; DSC3: 贴片; DSC4: CR1220-2; ERP Number: 1040100045; ID: 4; Part Name: 电池座; Part Number: J100303030001
L8 L46 = FB-0603: DSC1: 100Ω@100MHz; DSC2: 3A; DSC3: DCR=30mΩ; DSC4: 电源线; ERP Number: 1010200207; ID: 5; Manufacture: 顺络; Part Name: 贴片磁珠; Part Number: C060502370005; Price: 0.03
U6 = U-PCF85063ATT: DSC1: RTC,I2C, VCC=0.9-5.5V; DSC2: TSSOP8; DSC3: -40℃~+85℃; ID: 14; Manufacture: NXP; Part Name: RTC芯片; Part Number: C110203283829
XT1 = XTAL-2P: DSC1: 70kΩ; DSC2: ±20ppm; DSC3: 12.5pF; DSC4: -40℃~+85℃; DSC5: 3.2*1.5mm 2P; ID: 2; Manufacture: 泰晶; Part Name: 贴片无源晶振; Part Number: C050102290002; Price: 0.61
C154 C161 C167 C169 C171 C204 = C-0402: DSC1: ±10%; DSC2: 10V; DSC3: X7R; ID: 60; Manufacture: 三星|国巨|村田; Part Name: 贴片电容; Part Number: C020102120060; Price: 0.01
D66-D69 D74-D76 D80-D82 D85-D87 = DI-TVS-D: DSC1: 双向; DSC2: Vrwm=12V; DSC3: VBR=13.3V; DSC4: Vc=19.9V; DSC5: Ipp=20.1A; DSC6: Ppp=400W; ERP Number: 1010800028; ID: 5; Manufacture: MDD|伯恩半导体; Part Name: TVS; Part Number: C040602260005
D101-D103 D105 = DI-5TS075L_0: DSC1: 75V; DSC2: ±20%; DSC3: 5KA; DSC4: SMD,5x7.6mm; ERP Number: 1040100102; ID: 1; Manufacture: 良胜; Part Name: 放电管; Part Number: C040702270001; Price: 1.5
D110 = DI-TVS-D: DSC1: 双向; DSC2: Vrwm=40V; DSC3: VBR=44.4V; DSC4: Vc=64.5V; DSC5: Ipp=9.3A; DSC6: Ppp=800W; ID: 12; Manufacture: MDD|伯恩半导体; Part Name: TVS; Part Number: C040602260012
F6-F15 = FUSE-SMD1206: DSC1: 60V; DSC2: 0.1A; DSC3: SMD1206P010TF; DSC4: JK-NSMD010; ID: 5; Manufacture: BOURNS|金科; Part Name: 自恢复保险丝; Part Number: C160102670005; Price: 0.2
J9 = J-PCB-Con-12P: DSC1: 3.81mm间距; DSC2: 12P; DSC3: 通孔90度弯针; DSC4: 绿色; DSC5: WJ15EDGRC-3.81-12P(康奈克斯); ID: 50; Part Name: PCB插拔式接线端子; Part Number: J040204063841
J22 = J-A-3P_0: DSC1: 3p; DSC2: 1.25mm间距; DSC3: 卧贴; DSC4: 米黄色胶壳 耐高温; DSC5: A1251WR-S-3P(CJT); ID: 2; Part Name: MX1.25T; Part Number: J020102800040
J33 J59 = J-HDR-2: DSC1: 单排单塑; DSC2: 1x2; DSC3: 2mm脚距; DSC4: 通孔直针; DSC5: 针长8.8mm  2.8+2(H塑高)+4 mm; DSC6: 黑胶; ID: 66; Part Name: 单排针; Part Number: J010204073842
L36 = L-IND: DSC1: ±20%; DSC2: Isat=0.65A; DSC3: Irms=0.5A; DSC4: 1.092Ω; DSC5: 2.5*2.0*1.0mm; DSC6: SWPA252010S100MT(顺络); ERP Number: 1010200254; ID: 17; Manufacture: 顺络; Part Name: 功率电感; Part Number: C060202340017; Price: 0.19; Solder: 不推荐
L37-L40 L42-L45 = FB-0402: DSC1: 120Ω@100MHz; DSC2: 200mA; DSC3: DCR=400mΩ; DSC4: 低频信号; ERP Number: 1010200208; ID: 1; Manufacture: 顺络; Part Name: 贴片磁珠; Part Number: C060502370001; Price: 0.02
L41 = L-CMLS-ACM2012: DSC1: 90uH@100kHz; DSC2: 90Ω@100MHz; DSC3: 400mA; DSC4: DCR=300mΩ; DSC5: -40℃ ~ +125℃; DSC6: SMD_4P,2x1.2mm; ERP Number: 1010200196; ID: 1; Manufacture: 台庆; Part Name: 信号共模电感; Part Number: C060402360001; Price: 0.13
M2 = U-B0505S-1WR2_1: DSC1: Vi=4.5-5.5V; DSC2: Vo=5V; DSC3: 200mA; DSC4: 隔离型DC-DC; DSC5: 1.5KV隔离; ERP Number: 1010100146; ID: 2; Manufacture: 金升阳; Part Name: 电源模块; Part Number: C070502440002; Price: 6.2
R204 R243 = R-0402: DSC1: ±1%; DSC2: 1/16W; ID: 778; Part Name: 贴片电阻; Part Number: C011002080778; Price: 0.01
R205 R206 = R-0603: DSC1: ±1%; DSC2: 1/10W; ID: 1,339; Part Name: 贴片电阻; Part Number: C011002081339; Price: 0.01
R210 R214 R218 R221 = R-0603: DSC1: ±1%; DSC2: 1/10W; ID: 1,416; Part Name: 贴片电阻; Part Number: C011002081416; Price: 0.01
R212 R219 = R-1206: DSC1: ±1%; DSC2: 1/4W; ERP Number: 1010200271; ID: 1,999; Part Name: 贴片电阻; Part Number: C011002081999; Price: 0.01
R228 R229 R232-R234 R322-R325 = R-0402: DSC1: ±1%; DSC2: 1/16W; ID: 413; Part Name: 贴片电阻; Part Number: C011002080413; Price: 0.01
R337 = R-0402: DSC1: ±1%; DSC2: 1/16W; ERP Number: 1010200450; ID: 630; Part Name: 贴片电阻; Part Number: C011002080630; Price: 0.01
U19 = U-SP3232EEN-L-TR: DSC1: RS232 Transceiver up to 235kbps; DSC2: SOIC-16_150mil，1.27mm Pitch; DSC3: -40℃~+85℃; ERP Number: 1010100049; ID: 22; Manufacture: EXAR(艾科嘉); Part Name: RS232/RS485芯片; Part Number: C100302510001; Price: 0.91
U21 = U-122M31: DSC1: 2路隔离芯片,3~5.5V，1发1收，3KV隔离，10Mbps; DSC2: SOIC-8_150mil，1.27mm Pitch; DSC3: -40℃~+125℃; ID: 44; Manufacture: 荣湃; Part Name: 接口芯片; Part Number: C100603313834
U22 = U-TJA1057GT-3J: DSC1: CAN Transceiver, 5Mbps; DSC2: SOIC-8_150mil，1.27mm Pitch; DSC3: -40℃~+150℃; ERP Number: 1010100240; ID: 27; Manufacture: NXP; Part Name: CAN芯片; Part Number: C100402520002; Price: 4.6
U23 U24 = U-SP485EEN-L-TR: DSC1: RS485 Transceiver ,up to 10Mbps; DSC2: SOIC-8_150mil，1.27mm Pitch; DSC3: -40℃~+85℃; ERP Number: 1010100125; ID: 24; Manufacture: EXAR(艾科嘉); Part Name: RS232/RS485芯片; Part Number: C100302510003; Price: 0.77
U28 = U-142U31: DSC1: 4路隔离芯片,3~5.5V，2发2收，3KV隔离，150Kbps; DSC2: SOP16 10*3.9*1.5mm 1.27mm Pitch; DSC3: -40℃~+125℃; ID: 41; Manufacture: 荣湃; Part Name: 接口芯片; Part Number: C100603283831
U29 = U-162U31: DSC1: 6路隔离芯片,3~5.5V，4发2收，3KV隔离，150Kbps; DSC2: SOP16 10*3.9*1.5mm 1.27mm Pitc; DSC3: -40℃~+125℃; ID: 43; Manufacture: 荣湃; Part Name: 接口芯片; Part Number: C100603303832
C168 = C-0402: DSC1: ±5%; DSC2: 50V; DSC3: C0G; ERP Number: 1010200272; ID: 29; Manufacture: 三星|国巨|村田; Part Name: 贴片电容; Part Number: C020102120029; Price: 0.01
C181 C182 = C-0402: DSC1: ±5%; DSC2: 50V; DSC3: C0G; ERP Number: 1010200151; ID: 21; Manufacture: 三星|国巨|村田; Part Name: 贴片电容; Part Number: C020102120021; Price: 0.01
J12 = J-MINIPCIE-52P_0: DSC1: miniPCIE座子 H=8.0mm; DSC2: 52P; DSC3: 贴片; DSC4: 91304-80-052R2(UMaxconn); ID: 3; Part Name: 金手指连接器; Part Number: J050102900003
J39 = RF-IPEX-20279: DSC1: IPEX-20279-001E-01 板端贴片天线座 U.LF接头; DSC2: 贴片; ID: 1; Part Name: IPEX座; Part Number: J110103040001
R227 = R-0402: DSC1: ±1%; DSC2: 1/16W; ERP Number: 1010200458; ID: 875; Part Name: 贴片电阻; Part Number: C011002080875; Price: 0.01
R342 = R-0402: DSC1: ±1%; DSC2: 1/16W; ERP Number: 1010200099; ID: 595; Part Name: 贴片电阻; Part Number: C011002080595; Price: 0.01
SIM1 = J-SIM-021_0: DSC1: SIM卡座 91228 抽屉式 8P; DSC2: 31.0*25.1*26mm; DSC3: 贴片; DSC4: SIM-021(硕方); ERP Number: 1040100109; ID: 5; Part Name: SIM卡座; Part Number: J080202990002
U26 = eSIM
U27 = M-ATBM6032I_0: DSC1: L13.00*W12.20*H2.00mm; DSC3: IEEE 802.11b/g/n 1T1R; DSC4: 2.412-2.484GHz; ID: 4; Manufacture: 高拓讯达; Part Name: 无线模块; Part Number: C230404233852
J3 = J-HDR-D-40: DSC1: 双排单塑; DSC2: 2x20; DSC3: 2.54mm脚距; DSC4: 通孔直针; DSC5: 针长11.5mm 3+2.5(H塑高)+6mm; DSC6: 黑胶; DSC7: A2541WV-2x20P(CJT); ID: 64; Part Name: 双排针; Part Number: J010104013835
J8 = J-HDR-D-4: DSC1: 双排单塑; DSC2: 2x2; DSC3: 2mm脚距; DSC4: 通孔弯针; DSC5: 2.8+2(H塑高)+4 mm; DSC6: 黑胶; DSC7: A2005WR-2x2P（CJT); ERP Number: 1040100150; ID: 21; Part Name: 双排针; Part Number: J010102760077
J56 = J-HDR-D-30_1: DSC1: 双排单塑; DSC2: 2x16; DSC3: 2.54mm脚距; DSC4: 通孔直针; DSC5: 针长11.5mm 3+2.5(H塑高)+6mm; DSC6: 黑胶; DSC7: A2541WV-2x16P(CJT); ID: 52; Part Name: 双排针; Part Number: J010102760129
TP1 = TP-TEST: DSC1: 焊盘1.5mm; DSC2: 无孔; DSC3: 圆形; DSC4: 单面; ID: 5; Part Name: 测试点

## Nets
GND: C1.2 C2.1 C5.1 C6.1 C7.1 C9.1 C10.1 C11.1 C12.1 C14.1 C15.1 C18.1 C19.1 C20.1 C22.1 C23.1 C24.1 C25.1 C26.1 C27.1 C28.1 C29.1 C30.1 C32.1 C33.1 C40.1 C41.1 C42.1 C43.1 C44.1 C151.1 C154.1 C161.1 C167.1 C168.1 C169.1 C170.1 C171.1 C172.1 C173.1 C174.1 C175.1 C176.1 C177.1 C180.1 C181.1 C182.1 C185.1 C198.1 C204.1 C213.1 D1.A D8.2(I/O1) D9.2(I/O1) D10.2(I/O1) D11.2(I/O1) D12.2(I/O1) D13.2(I/O1) D14.2(I/O1) D62.2(I/O1) D63.2(I/O1) D90.2(I/O1) D91.2(I/O1) D92.2(I/O1) D93.2(I/O1) D94.2(I/O1) D95.2(I/O1) D111.2(I/O1) D112.2(I/O1) D119.2(I/O1) D120.2(I/O1) D123.2(I/O1) D124.2(I/O1) H5.1 J3.9 J3.10 J3.15 J3.16 J3.27 J3.28 J3.31 J3.32 J3.33 J3.35 J3.37 J4.6(VSS) J4.10(G1) J4.11(G2) J4.12(G3) J4.13(G4) J8.2 J8.4 J12.4(GND) J12.9(GND) J12.15(GND) J12.18(GND) J12.21(GND) J12.26(GND) J12.27(GND) J12.29(GND) J12.34(GND) J12.35(GND) J12.37(GND) J12.40(GND) J12.43(GND) J12.50(GND) J12.55(MT3) J12.56(MT4) J22.3 J22.4 J22.5 J39.1(GND1) J39.3(GND2) J39.4(GND3) J56.2(16) J56.5(3) J56.6(18) J56.32 J57.2(-) L1.3 LED2.4 M2.1(GND) Q2.2 Q3.2(SOURCE) Q4.2(SOURCE) Q8.2 Q18.2 Q22.2(SOURCE) Q23.2(SOURCE) R7.2 R11.2 R15.2 R21.2 R24.2 R213.2 R217.2 R349.2 SIM1.C5(GND) SW1.2 U1.1(VSS) U2.4(GND) U2.9(E-PAD) U3.1(GND) U4.2(GND) U5.2(GND) U6.4(VSS) U21.4(GND1) U26.1(VSS) U26.9(pad) U27.4(GND1) U27.5(GND2) U27.7(GND3) U28.2(GND1) U28.8(GND2) U29.8(GND1) ; also on sheet 5 6 7
GND_EARTH: D101.2 D102.2 D103.2 D105.2 H1.1 H2.1 H3.1 H4.1 H6.1 H7.1 ; also on sheet 6 7
VCC5V: BZ1.1(+) C9.2 C26.2 C29.2 C30.2 C151.2 J3.36 L36.1 Q1.3(DRAIN) U5.4(VIN) ; also on sheet 5 6
VCC_3V8: C31.2 C32.2 C33.2 C172.2 C173.2 C174.2 C175.2 C176.2 J12.2(VCC3V3) J12.24(NC3) J12.39(VCC3V3) J12.41(VCC3V3) J12.52(VCC3V3) L4.2 R19.1
VCC_RTC: C43.2 D121.C D122.C U6.8(VDD)
VCC_SD: C40.2 D124.1(I/O2) J4.4(VDD) L8.2
VCC_SIM: C169.2 C170.2 C204.2 D93.1(I/O2) L46.2 R226.2 R227.1 SIM1.C1(VDD) U26.8(VDD)
VDD_SNVS_3V3: C18.2 C185.2 D100.C R9.1 R16.1 U1.2(VOUT) U3.4(VCC) ; also on sheet 5
4G_LED_WANN#: D123.1(I/O2) J12.42(LED_WWAN) LED2.2
4G_PERST#: C171.2 J12.22(PERST_N) Q8.3
4G_PWREN_IO: R23.1 ; also on sheet 5
4G_RST_IO: Q8.1 ; also on sheet 5
485-2A/S2_TXD: D103.1 F6.2 F15.2 J9.4
485-2B/S2_RXD: D103.3 F7.2 F14.2 J9.5
B0: J56.13(7) R258.2
B1: J56.14(22) R260.2
B2: J56.15(8) R261.2
B3: J56.16(23) R263.2
B4: J56.17(9) R264.2
B5: J56.18(24) R265.2
BUZZER_PWM: C28.2 Q18.1 ; also on sheet 5
CAN1_H: L41.1 U22.7(CANH)
CAN1_L: L41.2 U22.6(CANL)
CAN1_RX: R204.2 U21.2(VOA) ; also on sheet 5
CAN1_RX_: U21.7(VIA) U22.4(RXD)
CAN1_STB_IO: R317.2 U22.8(S)
CAN1_TX: U21.3(VIB) ; also on sheet 5
CAN1_TX_: U21.6(VOB) U22.1(TXD)
CAN1H: D74.C(I/O1) D75.A(I/O2) F10.1 L41.4 R206.1
CAN1H_: D101.3 F10.2 J9.10
CAN1L: D75.C(I/O1) D76.C(I/O1) F11.1 L41.3 R205.1
CAN1L_: D101.1 F11.2 J9.11
CSI_DATA00/UART5_TX/SPI2_SLK: J3.8 ; also on sheet 5
CSI_DATA01/UART5_RX/SPI2_SS0: J3.7 ; also on sheet 5
CSI_DATA02/UART5_RTS/SPI2_MOSI: J3.6 ; also on sheet 5
CSI_DATA03/UART5_RTS/SPI2_MISO: J3.5 ; also on sheet 5
CSI_DATA04/SPI1_SCLK: J3.4 ; also on sheet 5
CSI_DATA05/SPI1_SS0: J3.3 ; also on sheet 5
CSI_DATA06/SPI1_MOSI: J3.2 ; also on sheet 5
CSI_DATA07/SPI1_MISO: J3.1 ; also on sheet 5
CSI_HSYNC: R67.1 R289.2 ; also on sheet 5
CSI_HSYNC/I2C_SCL/UART6_CTS/PWM8: J3.11 ; also on sheet 5
CSI_MCLK: R290.2 ; also on sheet 5
CSI_MCLK/I2C1_SDA/UART6_TX: J3.14 ; also on sheet 5
CSI_PIXCLK: R291.2 ; also on sheet 5
CSI_PIXCLK/I2C1_SCL/UART6_RX: J3.13 ; also on sheet 5
CSI_VSYNC: R66.1 R288.2 ; also on sheet 5
CSI_VSYNC/I2C_SDA/UART6_RTS/PWM7: J3.12 ; also on sheet 5
DC12V_IN: C1.1 C2.2 C5.2 C6.2 D1.C J3.38 L1.1 U1.3(VIN) U2.2(IN)
DCLK: C198.2 J56.7(4) R262.2
DE: J56.8(19) R266.2
DI: D110.C(I/O1) J9.12 R334.2 R335.2 R346.1
DN1: J56.3(2) ; also on sheet 6
DN3: J12.36(USB_D-) R228.1
DN4: R233.2 U27.2(D-)
DP1: J56.4(17) ; also on sheet 6
DP3: J12.38(USB_D+) R229.1
DP4: R234.2 U27.3(D+)
G0: J56.19(10) R267.2
G1: J56.20(25) R268.2
G2: J56.21(11) R270.2
G3: J56.22(26) R271.2
G4: J56.23(12) R272.2
G5: J56.24(27) R273.2
GPIO1_IO01: R294.1 R295.2 ; also on sheet 5
GPIO1_IO02: R293.1 R296.2 ; also on sheet 5
GPIO1_IO08: R269.1 ; also on sheet 5
GPIO-DI: R326.2 U28.6(VOD) ; also on sheet 5
GPIO-DI_: Q19.3(DRAIN) R333.2 R335.1 U28.11(VID)
GPIO_LCD_EN: R256.1 ; also on sheet 5
HSYNC: J56.10(20) R257.2
ISO_5V: C160.2 C164.2 C165.2 C191.2 C192.2 C193.2 C194.2 C195.2 J3.40 M2.4(VO+) R214.2 R221.2 R333.1 R334.1 U19.16(VCC) U21.8(VDD2) U22.3(VCC) U23.8(VCC) U24.8(VCC) U28.16(VDD2) U29.16(VDD2)
ISO_GND: C158.1 C159.1 C160.1 C163.1 C164.1 C165.1 C191.1 C192.1 C193.1 C194.1 C195.1 D66.A(I/O2) D67.A(I/O2) D68.A(I/O2) D69.A(I/O2) D74.A(I/O2) D76.A(I/O2) D81.A(I/O2) D82.A(I/O2) D85.A(I/O2) D87.A(I/O2) D110.A(I/O2) J3.39 J9.3 J9.6 J9.9 M2.3(0V) Q19.2(SOURCE) R210.1 R218.1 R220.2 R222.2 R317.1 R345.2 U19.15(GND) U21.5(GND2) U22.2(GND) U23.5(GND) U24.5(GND) U28.9(GND3) U28.15(GND4) U29.9(GND2)
JTAG_MOD: R217.1 U29.5(VID) ; also on sheet 5
LCD_DATA0: R258.1 ; also on sheet 5
LCD_DATA1: R260.1 ; also on sheet 5
LCD_DATA2: R261.1 ; also on sheet 5
LCD_DATA3: R263.1 ; also on sheet 5
LCD_DATA4: R264.1 ; also on sheet 5
LCD_DATA5: R265.1 ; also on sheet 5
LCD_DATA6: R267.1 ; also on sheet 5
LCD_DATA7: R268.1 ; also on sheet 5
LCD_DATA8: R270.1 ; also on sheet 5
LCD_DATA9: R271.1 ; also on sheet 5
LCD_DATA10: R272.1 ; also on sheet 5
LCD_DATA11: R273.1 ; also on sheet 5
LCD_DATA12: R274.1 ; also on sheet 5
LCD_DATA13: R275.1 ; also on sheet 5
LCD_DATA14: R276.1 ; also on sheet 5
LCD_DATA15: R277.1 ; also on sheet 5
LCD_DATA16: R278.1 ; also on sheet 5
LCD_DATA17: R279.1 ; also on sheet 5
LCD_DE: R266.1 ; also on sheet 5
LCD_EN: J56.12(21) R256.2
LCD_HSYNC: R257.1 ; also on sheet 5
LCD_PCLK: R262.1 ; also on sheet 5
LCD_PWM: J56.11(6) R269.2
LCD_VSYNC: R259.1 ; also on sheet 5
nSD_CD: D13.1(I/O2) J4.9(CD) R58.2 R64.2
Panel_VS: J56.9(5) R259.2
PMIC_ON_REQ: R10.1 ; also on sheet 5
PWR_EN: C14.2 D6.A Q4.1(GATE) R10.2 U2.7(EN)
PWR_IN_N: J30.2 L1.4 MOV1.2(K)
PWR_IN_P: F1.1 J30.1 MOV1.1(A)
R0: J56.25(13) R274.2
R1: J56.26(28) R275.2
R2: J56.27(14) R276.2
R3: J56.28(29) R277.2
R4: J56.29(15) R278.2
R5: J56.30 R279.2
RS485-1A: D102.1 F13.2 J9.1
RS485-1B: D102.3 F12.2 J9.2
RS485_EN_1: R213.1 U29.3(VIB) ; also on sheet 5
RS485X1_DIN_: U23.4(DI) U29.15(VOA)
RS485X1_DM: L42.1 R210.2 U23.7(B)
RS485X1_DOUT_: U23.1(RO) U29.11(VIE)
RS485X1_DP: L43.1 R214.1 U23.6(A)
RS485X1_RW_EN_: R220.1 U23.2(\\~{R}E) U23.3(DE) U29.14(VOB)
RS485X2_DIN_: R322.1 R325.1 U29.13(VOC)
RS485X2_DM: L44.1 R218.2 U24.7(B)
RS485X2_DOUT_: R323.1 R324.1 U29.10(VIF)
RS485X2_DP: L45.1 R221.1 U24.6(A)
RS485X2_RW_EN_: R222.1 U24.2(\\~{R}E) U24.3(DE) U29.12(VOD)
RST_BIN: R315.1
RTC_SCL: R67.2 U6.6(SCL)
RTC_SDA: R66.2 U6.5(SDA)
RTC_VBAT: D122.A J57.1(+)
S2RX: D68.C(I/O1) F7.1 L38.2
S2TX: D69.C(I/O1) F6.1 L37.2
S3_RXD: D105.3 F9.2 J9.8
S3_TXD: D105.1 F8.2 J9.7
S3RX: D66.C(I/O1) F9.1 L40.2
S3TX: D67.C(I/O1) F8.1 L39.2
SD1_CLK: R65.1 ; also on sheet 5
SD1_CMD: R63.1 ; also on sheet 5
SD1_DATA0: R59.1 ; also on sheet 5
SD1_DATA1: R60.1 ; also on sheet 5
SD1_DATA2: R61.1 ; also on sheet 5
SD1_DATA3: R62.1 ; also on sheet 5
SD2_CLK/PWM6: J3.21 ; also on sheet 5
SD2_CMD/PWM5: J3.22 ; also on sheet 5
SD2_D0/UART8_TX/SPI1_SCLK: J3.17 ; also on sheet 5
SD2_D1/UART8_RX/SPI1_SS0: J3.18 ; also on sheet 5
SD2_D2/SPI1_MOSI: J3.19 ; also on sheet 5
SD2_D3/SPI1_MISO: J3.20 ; also on sheet 5
SD_CLK: C41.2 D14.1(I/O2) J4.5(CLK) R65.2
SD_CMD: D12.1(I/O2) J4.3(CMD) R57.2 R63.2
SD_D0: D8.1(I/O2) J4.7(DATA0) R56.2 R59.2
SD_D1: D9.1(I/O2) J4.8(DATA1) R60.2
SD_D2: D10.1(I/O2) J4.1(DATA2) R61.2
SD_D3: D11.1(I/O2) J4.2(CD/DATA3) R62.2
SIM_CLK: C168.2 D91.1(I/O2) R224.2 SIM1.C3(CLK) U26.6(CLK)
SIM_DATA: D92.1(I/O2) R223.2 R227.2 SIM1.C7(DATA) U26.3(I/O)
SIM_RST: D90.1(I/O2) R225.2 R226.1 SIM1.C2(RESET) U26.7(RST)
SNVS_TAMPER5: R236.1 ; also on sheet 5
SNVS_TAMPER7: Q23.1(GATE) R349.1 ; also on sheet 5
SNVS_TAMPER9: R340.1 ; also on sheet 5
SYS_3V3: C21.2 C22.2 C23.2 C24.2 C25.2 C154.2 C161.2 C167.2 C213.2 C214.2 D100.A D121.A J3.34 J56.31 L3.2 L8.1 Q2.1 Q21.2(SOURCE) R13.1 R14.1 R20.1 R22.1 R56.1 R57.1 R58.1 R203.1 R204.1 R209.2 R211.2 R215.2 R216.2 R235.1 R243.1 R288.1 R289.1 R290.1 R291.1 R295.1 R296.1 R326.1 R341.1 U21.1(VDD1) U28.1(VDD1) U29.1(VDD1) ; also on sheet 5 6 7
SYS_5V: C7.2 C8.2 C10.2 C11.2 C12.2 C19.2 C20.2 L2.2 Q1.2(SOURCE) R5.1 R6.1 U4.1(EN) U4.4(VIN)
UART1_RTS: R64.1 ; also on sheet 5
UART1_RX_DATA: D61.A R243.2 ; also on sheet 5
UART1_TX_DATA: R337.1 ; also on sheet 5
UART2_CTS/CAN2_TX: J3.25 ; also on sheet 5
UART2_RTS/CAN2_RX: J3.26 ; also on sheet 5
UART2_RX_DATA: J3.24 ; also on sheet 5
UART2_RXD_: R323.2 U19.12(R1OUT)
UART2_TX_DATA: J3.23 ; also on sheet 5
UART2_TXD_: R322.2 U19.11(T1IN)
UART3_RX_DATA: R203.2 U28.5(VOC) ; also on sheet 5
UART3_RXD_: U19.9(R2OUT) U28.12(VIC)
UART3_TX_DATA: U28.4(VIB) ; also on sheet 5
UART3_TXD_: U19.10(T2IN) U28.13(VOB)
UART4_RX_DATA: R211.1 U29.6(VOE) ; also on sheet 5
UART4_TX_DATA: R209.1 U29.2(VIA) ; also on sheet 5
UART5_RX_DATA: R216.1 U29.7(VOF) ; also on sheet 5
UART5_TX_DATA: R215.1 U29.4(VIC) ; also on sheet 5
USB_5V: J56.1 TP1.1 ; also on sheet 6
USB_A2_DN: J3.30 ; also on sheet 6
USB_A2_DP: J3.29 ; also on sheet 6
USB_A3_DN: R228.2 ; also on sheet 6
USB_A3_DP: R229.2 ; also on sheet 6
USB_A4_DN: R233.1 ; also on sheet 6
USB_A4_DP: R234.1 ; also on sheet 6
USER_IO01: D120.1(I/O2) J8.1 R294.2
USER_IO02: D119.1(I/O2) J8.3 R293.2
WIFI_3V3: C177.2 C180.2 Q21.3(DRAIN) R342.1 U27.1(3V3)
WIFI_ANT: C182.2 D94.1(I/O2) J39.2(SIG) R232.2
N09303: F1.2 L1.2
N15815: Q2.3 R8.1
N15819: C8.1 Q1.1(GATE) R5.2 R8.2
N17403: L3.1 U4.3(SW)
N17407: C21.1 R13.2 R15.1 U4.5(FB)
N18430: C27.2 Q3.1(GATE) Q4.3(DRAIN) R16.2
N19026: Q3.3(DRAIN) R14.2
N19455: D6.C U3.2(RSET#)
N172815: C44.2 U6.2(OSCO) XT1.2
N172819: C42.2 U6.1(OSCI) XT1.1
N176701: C156.2 U19.1(C1+)
N176705: C156.1 U19.3(C1-)
N176712: C157.2 U19.4(C2+)
N176716: C157.1 U19.5(C2-)
N176723: C158.2 U19.2(V+)
N176739: C159.2 U19.6(V-)
N177083: L37.1 U19.14(T1OUT)
N177087: L38.1 U19.13(R1IN)
N177091: L39.1 U19.7(T2OUT)
N177095: L40.1 U19.8(R2IN)
N185992: D80.A(I/O2) D81.C(I/O1) F12.1 L42.2 R212.1
N185996: D80.C(I/O1) D82.C(I/O1) F13.1 J33.2 L43.2
N187746: J33.1 R212.2
N190400: D85.C(I/O1) D86.A(I/O2) F14.1 L44.2 R219.1
N190404: D86.C(I/O1) D87.C(I/O1) F15.1 J59.2 L45.2
N190796: J59.1 R219.2
N205861: J12.10(USIM_IO) R223.1
N205865: J12.12(USIM_CLK) R224.1
N205869: J12.14(USIM_RESET) R225.1
N206387: J12.8(VREG_USIM) L46.1
N292305: R23.2 R24.1 U5.1(EN)
N292361: L4.1 U5.3(SW)
N292365: C31.1 R19.2 R21.1 U5.5(FB)
N424759: C163.2 R205.2 R206.2
N430768: D112.1(I/O2) LED2.3 Q23.3(DRAIN) R20.2
N430772: D111.1(I/O2) LED2.1 R22.2
N466301: C4.1 U2.1(BS)
N466320: C4.2 L2.1 U2.3(SW)
N466802: R6.2 R7.1 U2.5(FB)
N467179: C15.2 U2.8(SS)
N480384: C16.1 R11.1
N480388: C16.2 U2.6(COMP)
N486758: L36.2 M2.2(VIN)
N556991: R9.2 R315.2 U3.3(MR#)
N571997: D95.1(I/O2) R235.2 R236.2 SW1.1
N708171: D62.1(I/O2) J22.2 R337.2
N708293: D61.C D63.1(I/O2) J22.1
N899038: BZ1.2(-) Q18.3
N942700: R324.2 U24.1(RO)
N942704: R325.2 U24.4(DI)
N946162: Q19.1(GATE) R345.1 R346.2
N971048: C214.1 Q21.1(GATE) Q22.1(GATE) R340.2 R341.2
N985044: Q22.3(DRAIN) R342.2
N1098962: C181.2 R232.1 U27.6(ANT)

Not connected (* = marked no-connect by the designer): J12 1(MICP)* 3(MICN)* 5(EARP)* 6(NC1)* 7(EARN)* 11(UART1_RX)* 13(UART1_TX)* 16(NC2)* 17(UART1_R1)* 19(WAKEUP_N)* 20(W_DISABLE_N)* 23(UART1_CTS)* 25(UART1_RFR)* 28(NC4)* 30(UART2_RFR)* 31(UART1_DTR)* 32(UART2_CTS)* 33(UART1_DCD)* 44(UART2_RX)* 45(AUX_PCM_CLK)* 46(UART2_TX)* 47(AUX_PCM_DOUT)* 48(NC5)* 49(AUX_PCM_DIN)* 51(AUX_PCM_SYNC)* 53(MT1) 54(MT2); MARK1 1; MARK2 1; MARK3 1; MARK4 1; SIM1 C6(VPP)* CD1 CD2; SW1 3 4; U6 3(\~{IN}T)* 7(CLKOUT)*; U22 5(VIO/NC); U26 2(NC1)* 4(NC3)* 5(NC2)*; U27 8(XTAL_P); U28 3(VIA) 7(NC1)* 10(NC2)* 14(VOA)

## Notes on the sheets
sheet 8
- EXPAND
- 电阻靠近核心板引脚放置
sheet 9
- 4G-MODE
- WIFI
sheet 10
- TF_CARD
- RTC
sheet 11
- DEBUG
- RS232
- CAN
- RS485
sheet 12
- VDD_SNVS_3V3
- KEY-IO
- DC12V_IN
- 5V-BUFFER
- BUZZER
- SYS_5V
- VFB=0.925V
- VCC5V
- RESET
- SYS_3V3
- 泄电电路，可选
- LED
- VCC_3V8
- MARK
